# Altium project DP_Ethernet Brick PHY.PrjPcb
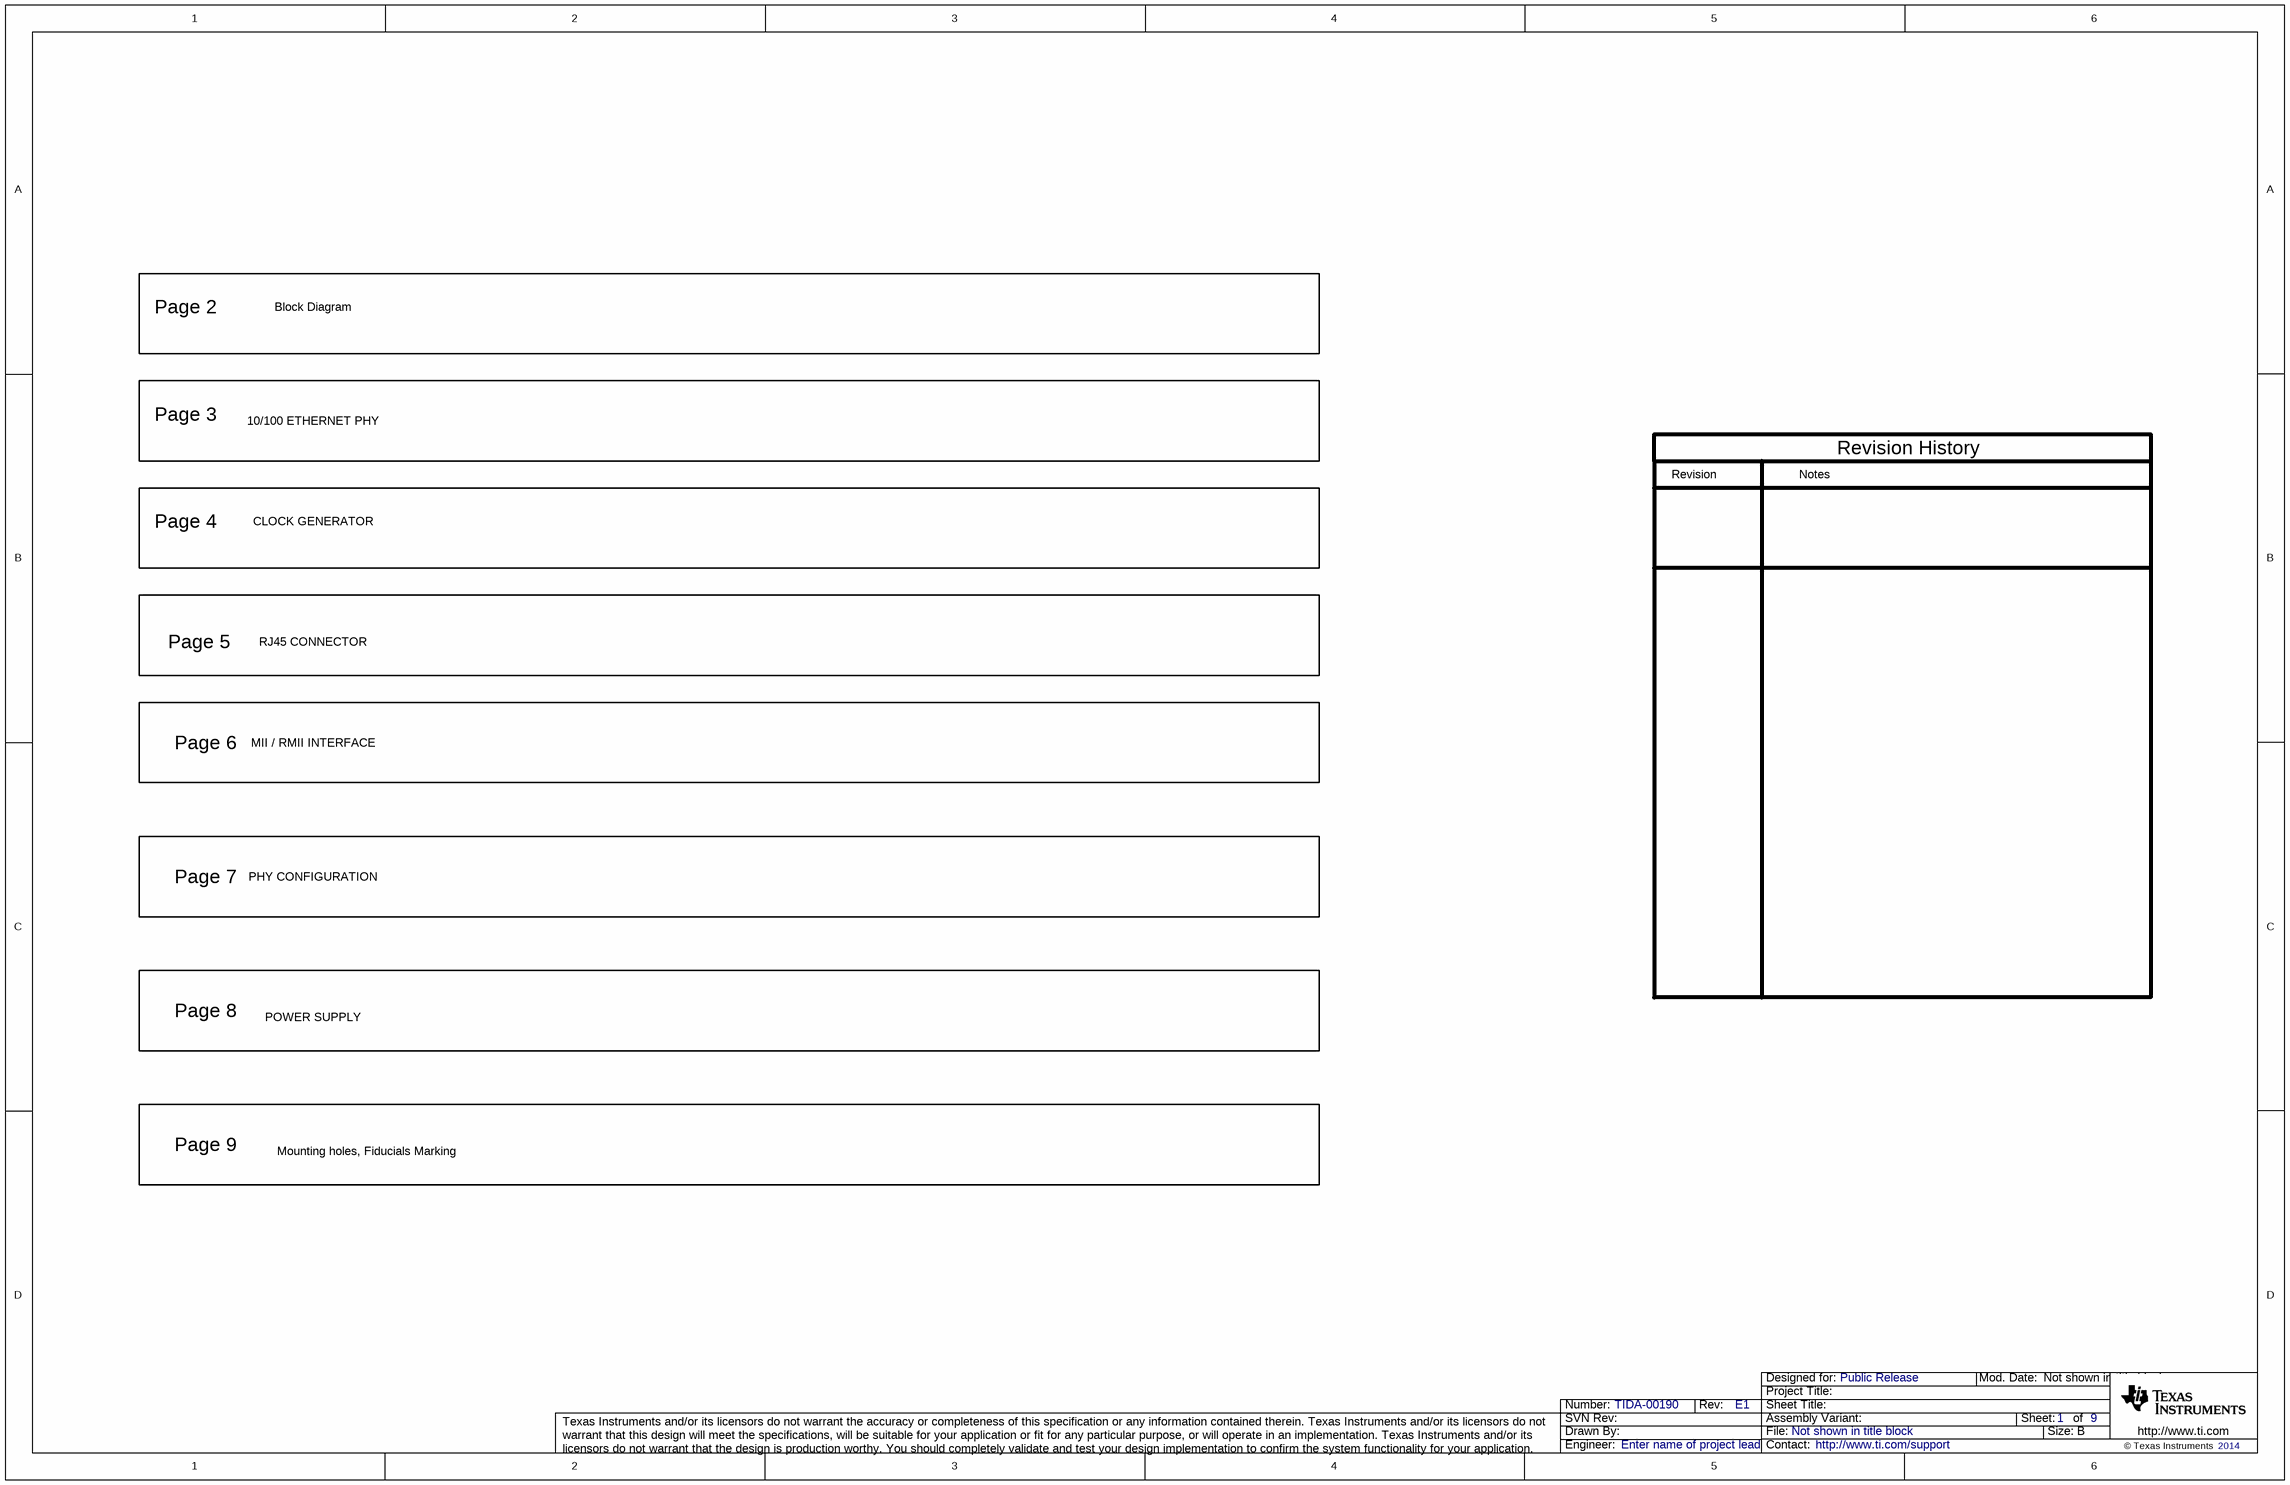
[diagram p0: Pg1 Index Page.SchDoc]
CopyrightYear: 2014; PCB_Layout: Who did the Layout?; PCB_Rev: E1; PRJ_Customer: Public Release; PRJ_Engineer: Enter name of project lead; PRJ_Number: TIDA-00190; SCH_Rev: E1; TechSupport: http://www.ti.com/support
9 sheets, 178 parts. Net scope: global (net labels, ports and power ports of the same name join across sheets).
Board file: ISE3009.PcbDoc
Sheets:
  Pg1 Index Page.SchDoc
  Pg2.SchDoc
  Pg3.SchDoc
  Pg4.SchDoc
  Pg5.SchDoc
  Pg6.SchDoc
  Pg7.SchDoc
  Pg8.SchDoc
  Pg9 Hardware.SchDoc

## Sheet Pg1 Index Page.SchDoc
size 431 x 279 mm; Date: Not shown in title block; ApprovedBy: Not shown in title block; CheckedBy: Not shown in title block; Author: Not shown in title block; CompanyName: Not shown in title block; Engineer: Not shown in title block; Organization: Not shown in title block; Address1: Not shown in title block; Address2: Not shown in title block; Address3: Not shown in title block; Address4: Not shown in title block; DocumentNumber: 1; Revision: Use project parameter SCH_Rev; SheetNumber: 1; SheetTotal: 9; PageSetup: Record=PageOptions|CenterHorizontal=True|CenterVertical=True|PrintScale=1.00|XCorrection=1.00|YCorrection=1.00|PrintKind=0|BorderSize=5000000|LeftOffset=0|BottomOffset=0|Orientation=2|PaperLength=1000|PaperWidth=1000|Scale=100|PaperSource=15|PrintQuality=600|MediaType=1|DitherType=10|PaperKind=Letter|PrintScaleMode=1

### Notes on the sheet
- Page 2
- Block Diagram
- Page 3
- 10/100 ETHERNET PHY
- Revision
- Notes
- Revision History
- Page 4
- CLOCK GENERATOR
- Page 5
- RJ45 CONNECTOR
- Page 6
- MII / RMII INTERFACE
- Page 7
- PHY CONFIGURATION
- Page 8
- POWER SUPPLY
- Page 9
- Mounting holes, Fiducials Marking

## Sheet Pg2.SchDoc
size 431 x 279 mm; Date: Not shown in title block; ApprovedBy: Not shown in title block; CheckedBy: Not shown in title block; Author: Not shown in title block; CompanyName: Not shown in title block; Engineer: Not shown in title block; Organization: Not shown in title block; Address1: Not shown in title block; Address2: Not shown in title block; Address3: Not shown in title block; Address4: Not shown in title block; DocumentNumber: 2; Revision: Use project parameter SCH_Rev; SheetNumber: 2; SheetTotal: 9; PageSetup: Record=PageOptions|CenterHorizontal=True|CenterVertical=True|PrintScale=1.00|XCorrection=1.00|YCorrection=1.00|PrintKind=0|BorderSize=5000000|LeftOffset=0|BottomOffset=0|Orientation=2|PaperLength=1000|PaperWidth=1000|Scale=100|PaperSource=15|PrintQuality=600|MediaType=1|DitherType=10|PaperKind=Letter|PrintScaleMode=1
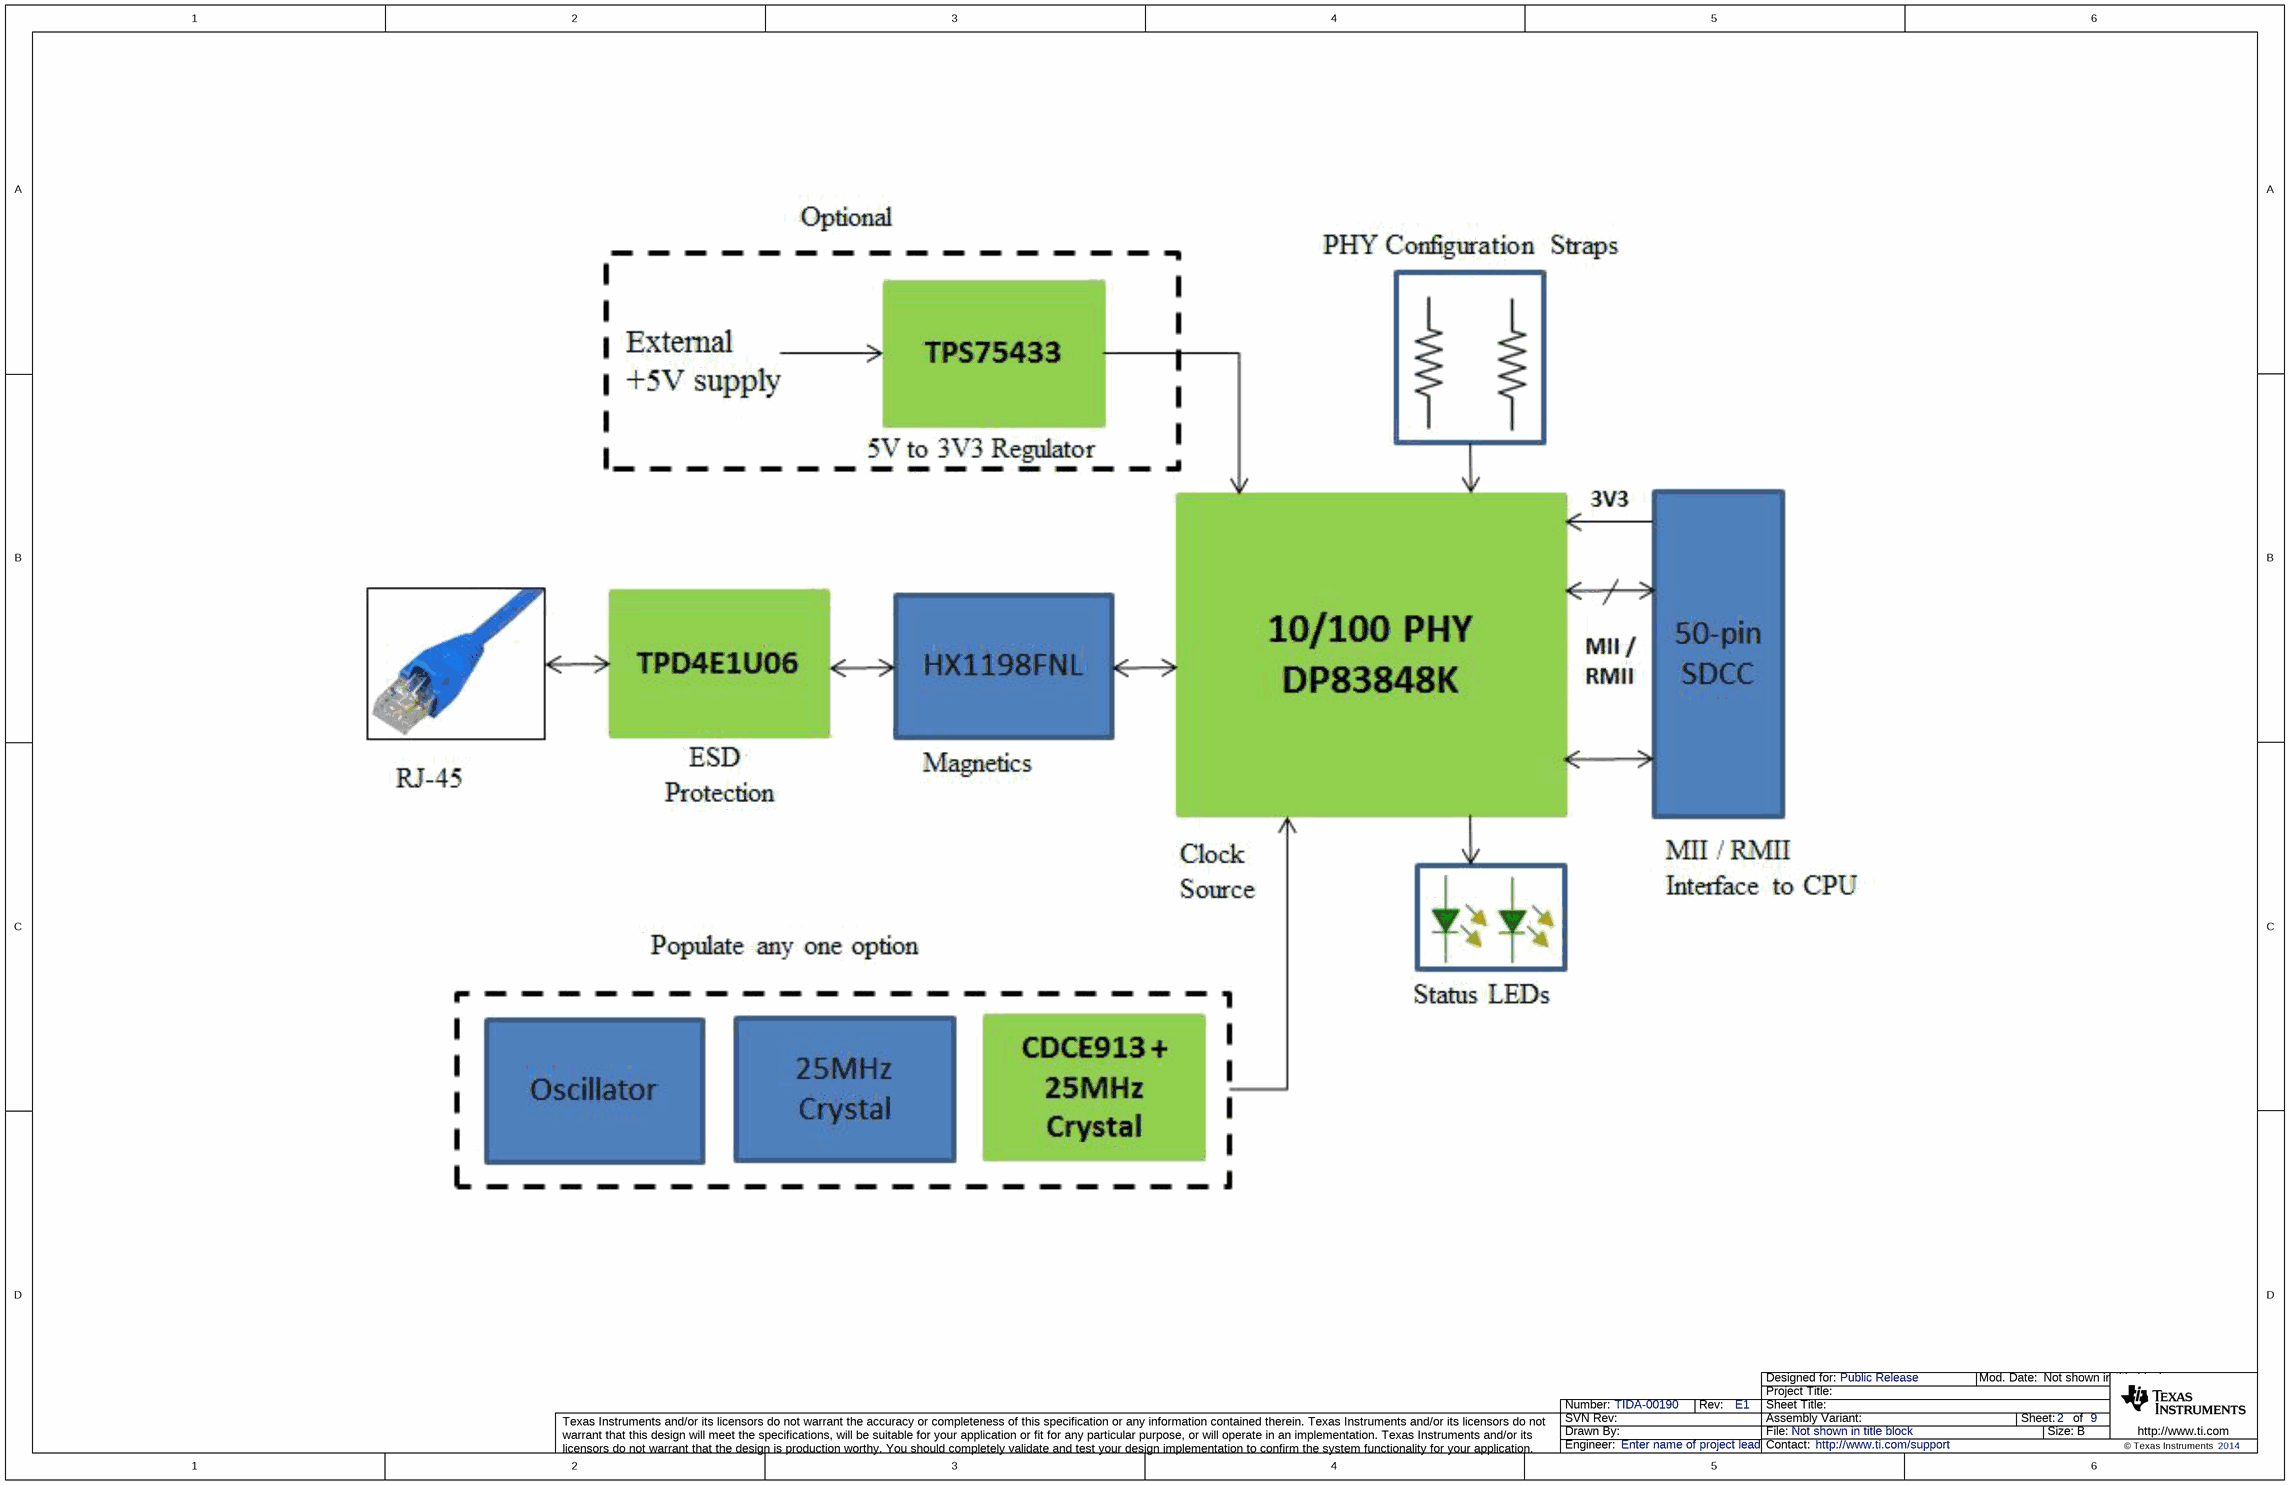
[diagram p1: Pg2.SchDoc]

## Sheet Pg3.SchDoc: 10/100 Ethernet PHY - DP83848J
size 558 x 431 mm; DocumentNumber: 9; SheetNumber: 3; SheetTotal: 9; PageSetup: Record=PageOptions|CenterHorizontal=True|CenterVertical=True|PrintScale=1.00|XCorrection=1.00|YCorrection=1.00|PrintKind=0|BorderSize=5000000|LeftOffset=0|BottomOffset=0|Orientation=2|PaperLength=1000|PaperWidth=1000|Scale=100|PaperSource=15|PrintQuality=600|MediaType=1|DitherType=10|PaperKind=Letter|PrintScaleMode=1
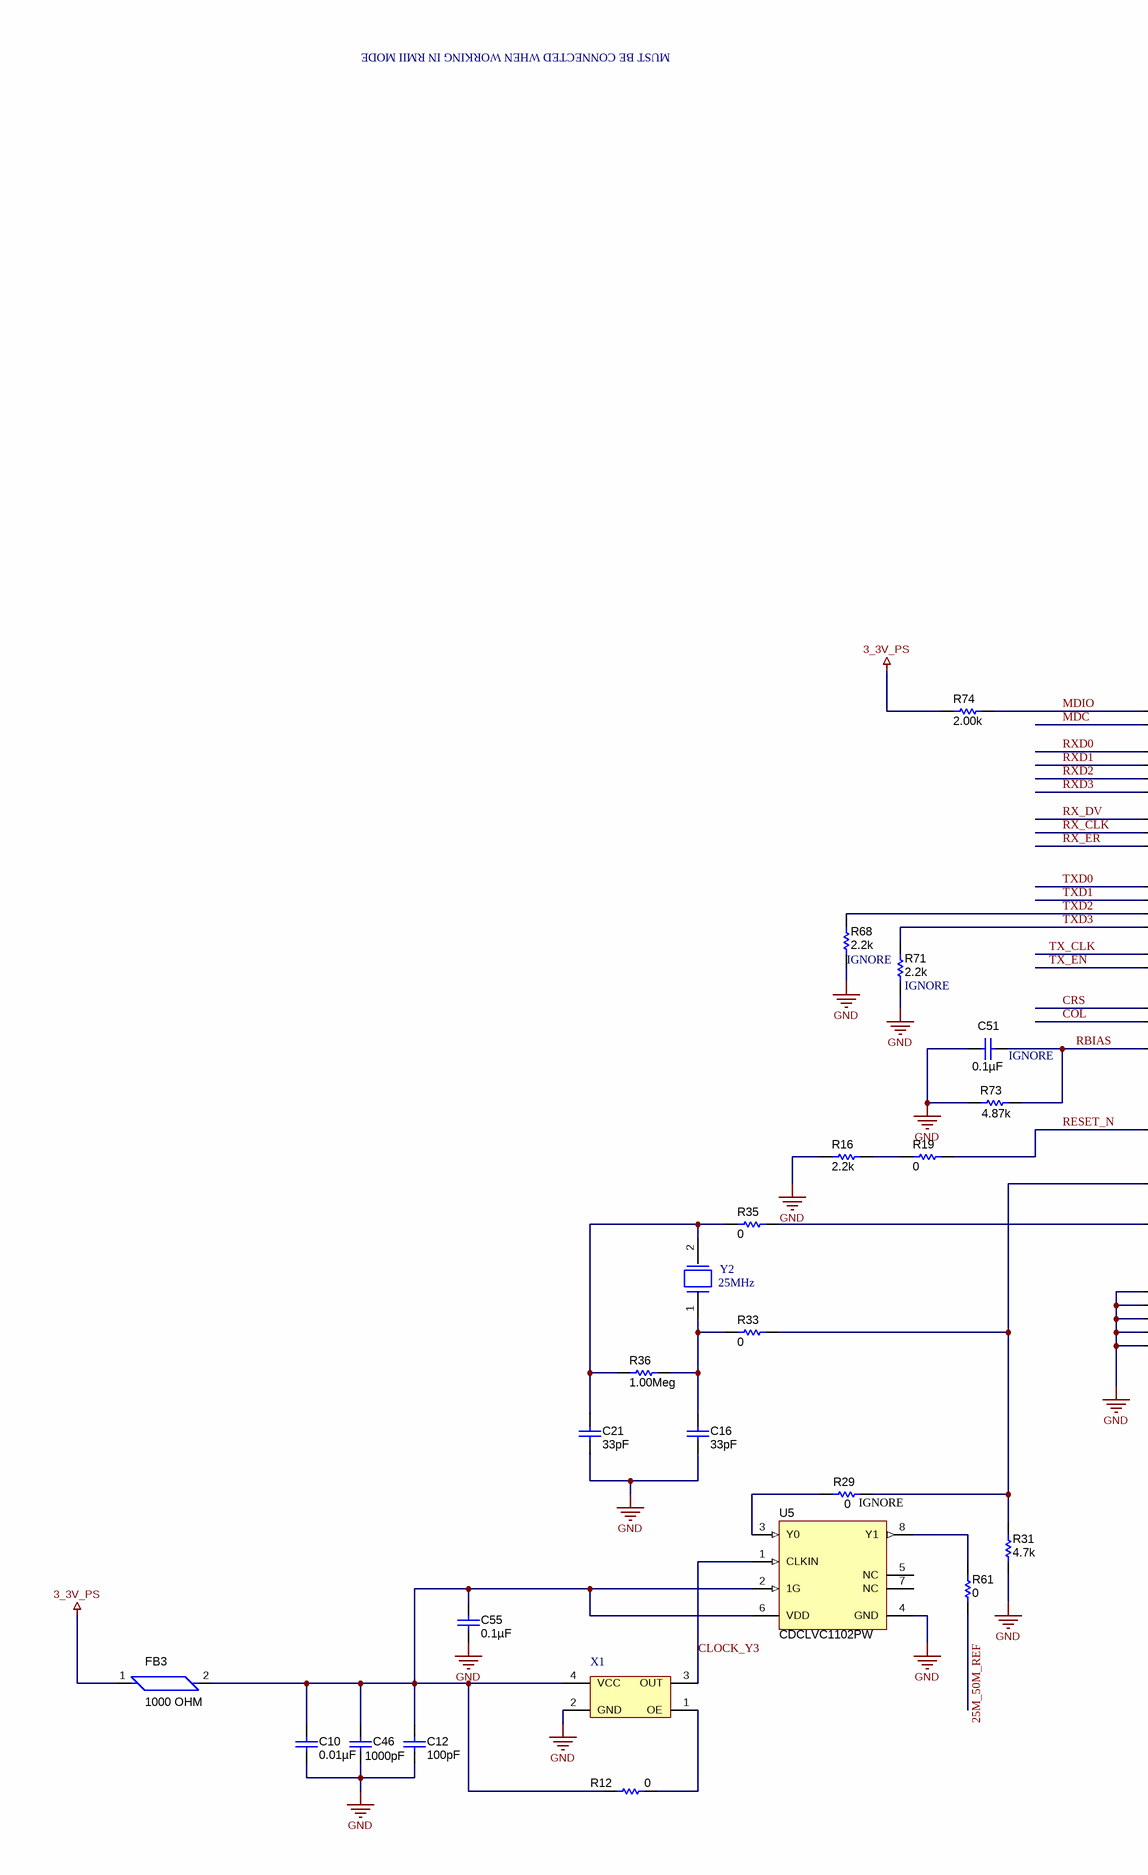
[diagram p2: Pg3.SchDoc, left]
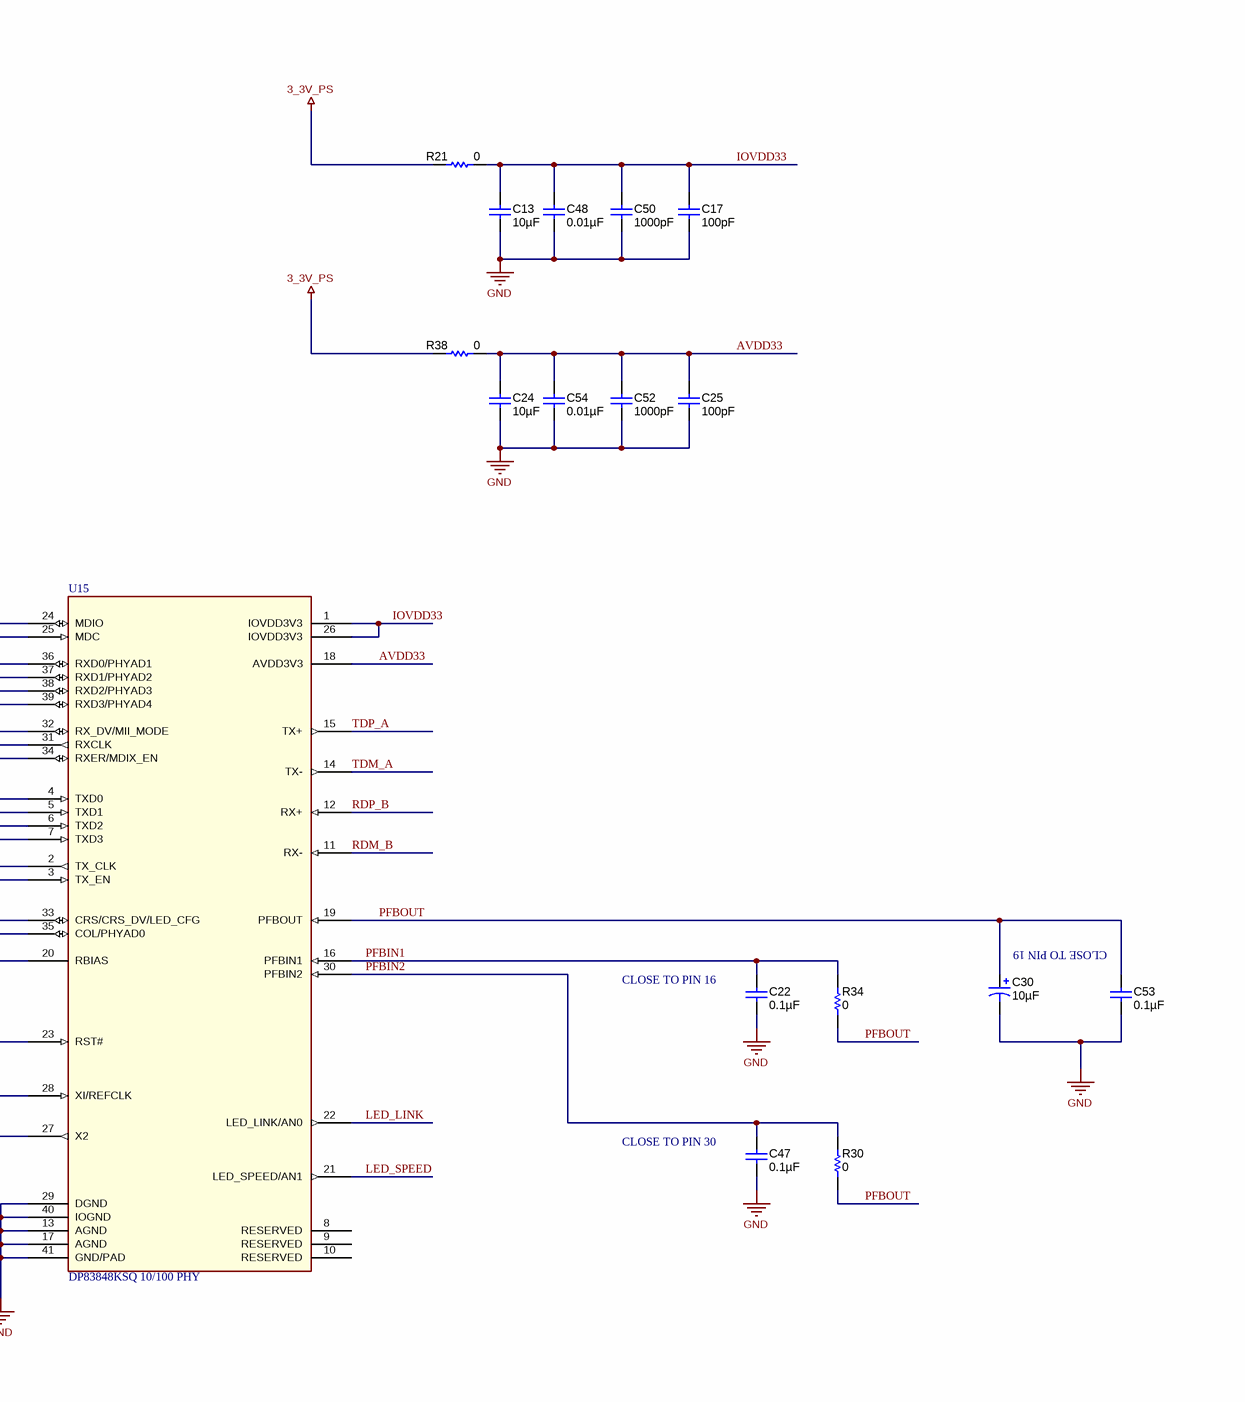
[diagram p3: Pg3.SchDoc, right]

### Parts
C10  ValueDisplayed: 0.01µF  [0402]  (hidden comment: GCM155R71H103KA55D)
C12  ValueDisplayed: 100pF  [0402]  (hidden comment: CC0402KRX7R9BB101)
C13  ValueDisplayed: 10µF  [1206]  (hidden comment: GMK316AB7106KL)
C16  ValueDisplayed: 33pF  [0603]  (hidden comment: 06035A330JAT2A)
C17  ValueDisplayed: 100pF  [0402]  (hidden comment: CC0402KRX7R9BB101)
C21  ValueDisplayed: 33pF  [0603]  (hidden comment: 06035A330JAT2A)
C22  ValueDisplayed: 0.1µF  [0603]  (hidden comment: C0603C104K4RACTU)
C24  ValueDisplayed: 10µF  [1206]  (hidden comment: GMK316AB7106KL)
C25  ValueDisplayed: 100pF  [0402]  (hidden comment: CC0402KRX7R9BB101)
C30  ValueDisplayed: 10µF  [3528-21]  (hidden comment: 293D106X9016B2TE3)
C46  ValueDisplayed: 1000pF  [0402]  (hidden comment: GRM155R61E102KA01D)
C47  ValueDisplayed: 0.1µF  [0603]  (hidden comment: C0603C104K4RACTU)
C48  ValueDisplayed: 0.01µF  [0402]  (hidden comment: GCM155R71H103KA55D)
C50  ValueDisplayed: 1000pF  [0402]  (hidden comment: GRM155R61E102KA01D)
C51  ValueDisplayed: 0.1µF  [0603]  (hidden comment: C0603C104K4RACTU)
C52  ValueDisplayed: 1000pF  [0402]  (hidden comment: GRM155R61E102KA01D)
C53  ValueDisplayed: 0.1µF  [0603]  (hidden comment: C0603C104K4RACTU)
C54  ValueDisplayed: 0.01µF  [0402]  (hidden comment: GCM155R71H103KA55D)
C55  ValueDisplayed: 0.1µF  [0603]  (hidden comment: C0603C104K4RACTU)
FB3  1000 OHM  [FB0603]
R12  value 0  [0603]  (hidden comment: CRCW06030000Z0EA)
R16  value 2.2k  [0402]  (hidden comment: CRCW04022K20JNED)
R19  value 0  [0603]  (hidden comment: CRCW06030000Z0EA)
R21  value 0  [0805_HV]  (hidden comment: RC0805JR-070RL)
R29  value 0  [0603]  (hidden comment: CRCW06030000Z0EA)
R30  value 0  [0805_HV]  (hidden comment: RC0805JR-070RL)
R31  value 4.7k  [0603]  (hidden comment: RC0603JR-074K7L)
R33  value 0  [0603]  (hidden comment: CRCW06030000Z0EA)
R34  value 0  [0805_HV]  (hidden comment: RC0805JR-070RL)
R35  value 0  [0603]  (hidden comment: CRCW06030000Z0EA)
R36  value 1.00Meg  [0402]  (hidden comment: CRCW04021M00FKED)
R38  value 0  [0805_HV]  (hidden comment: RC0805JR-070RL)
R61  value 0  [0603]  (hidden comment: CRCW06030000Z0EA)
R68  value 2.2k  [0402]  (hidden comment: CRCW04022K20JNED)
R71  value 2.2k  [0402]  (hidden comment: CRCW04022K20JNED)
R73  value 4.87k  [0603]  (hidden comment: CRCW06034K87FKEA)
R74  value 2.00k  [0402]  (hidden comment: CRCW04022K00FKED)
U5  CDCLVC1102PW  [PW0008A_N]
U15  DP83848KSQ 10/100 PHY  [QFN50P600X600X80-40N]
X1  HG-2150CA 25.000M-BXC3  [OSC_HG-2150CA]  (value not drawn)
Y2  value 25MHz  [XTAL_ATS250BSM-1E_1]  (hidden comment: XTAL-445I23D25M00000)

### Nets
3_3V_PS: FB3.1 R21.1 R38.1 R74.1
GND: C10.2 C12.2 C13.2 C16.2 C17.2 C21.2 C22.2 C24.2 C25.2 C30.2(-) C46.2 C47.2 C48.2 C50.2 C51.1 C52.2 C53.2 C54.2 C55.2 R16.2 R31.1 R68.1 R71.1 R73.1 U5.4(GND) U15.13(AGND) U15.17(AGND) U15.29(DGND) U15.40(IOGND) U15.41(GND/PAD) X1.2(GND)
25M_50M_REF: R61.1
AVDD33: C24.1 C25.1 C52.1 C54.1 R38.2 U15.18(AVDD3V3)
CLOCK_Y3: U5.1(CLKIN) X1.3(OUT)
COL: U15.35(COL/PHYAD0)
CRS: U15.33(CRS/CRS_DV/LED_CFG)
IOVDD33: C13.1 C17.1 C48.1 C50.1 R21.2 U15.1(IOVDD3V3) U15.26(IOVDD3V3)
LED_LINK: U15.22(LED_LINK/AN0)
LED_SPEED: U15.21(LED_SPEED/AN1)
MDC: U15.25(MDC)
MDIO: R74.2 U15.24(MDIO)
PFBIN1: C22.1 R34.2 U15.16(PFBIN1)
PFBIN2: C47.1 R30.2 U15.30(PFBIN2)
PFBOUT: C30.1(+) C53.1 R30.1 R34.1 U15.19(PFBOUT)
RBIAS: C51.2 R73.2 U15.20(RBIAS)
RDM_B: U15.11(RX-)
RDP_B: U15.12(RX+)
RESET_N: R19.2 U15.23(RST#)
RX_CLK: U15.31(RXCLK)
RX_DV: U15.32(RX_DV/MII_MODE)
RX_ER: U15.34(RXER/MDIX_EN)
RXD0: U15.36(RXD0/PHYAD1)
RXD1: U15.37(RXD1/PHYAD2)
RXD2: U15.38(RXD2/PHYAD3)
RXD3: U15.39(RXD3/PHYAD4)
TDM_A: U15.14(TX-)
TDP_A: U15.15(TX+)
TX_CLK: U15.2(TX_CLK)
TX_EN: U15.3(TX_EN)
TXD0: U15.4(TXD0)
TXD1: U15.5(TXD1)
TXD2: R68.2 U15.6(TXD2)
TXD3: R71.2 U15.7(TXD3)
NetC10_1: C10.1 C12.1 C46.1 C55.1 FB3.2 R12.1 U5.2(1G) U5.6(VDD) X1.4(VCC)
NetC16_1: C16.1 R33.2 R36.2 Y2.1
NetC21_1: C21.1 R35.2 R36.1 Y2.2
NetR12_2: R12.2 X1.1(OE)
NetR16_1: R16.1 R19.1
NetR29_1: R29.1 U5.3(Y0)
NetR29_2: R29.2 R31.2 R33.1 U15.28(XI/REFCLK)
NetR35_1: R35.1 U15.27(X2)
NetR61_2: R61.2 U5.8(Y1)

Not connected (* = marked no-connect by the designer): U5 5(NC) 7(NC); U15 8(RESERVED) 9(RESERVED) 10(RESERVED)

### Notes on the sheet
- MUST BE CONNECTED WHEN WORKING IN RMII MODE
- (near C22) CLOSE TO PIN 16
- CLOSE TO PIN 19
- (near C47) CLOSE TO PIN 30

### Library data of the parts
C10 C48 C54 = GCM155R71H103KA55D: CAP, CERM, 0.01uF, 50V, +/-10%, C0G/NP0, 0402; Manufacturer: MuRata; Polarized: N; CompType: Capacitor; U/M: EA; Cap_F: 0.00000001; Tolerance_%: 10; Value1: Unknown; VDC_V: 50; TaMin_C: -55; TaMax_C: 125
C12 C17 C25 = CC0402KRX7R9BB101: CAP, CERM, 100pF, 50V, +/-10%, X7R, 0402; Manufacturer: Yageo America; Polarized: N; CompType: Capacitor; U/M: EA; Cap_F: 0.0000000001; Tolerance_%: 10; Value1: Unknown; VDC_V: 50; TaMin_C: -55; TaMax_C: 125
C13 C24 = GMK316AB7106KL: CAP, CERM, 10uF, 35V, +/-10%, X7R, 1206; Manufacturer: Taiyo Yuden; Polarized: N; CompType: Capacitor; U/M: EA; Cap_F: 0.00001; Tolerance_%: 10; Value1: Unknown; VDC_V: 35; TaMin_C: -55; TaMax_C: 125
C16 C21 = 06035A330JAT2A: CAP, CERM, 33pF, 50V, +/-5%, C0G/NP0, 0603; Manufacturer: AVX; Polarized: N; CompType: Capacitor; U/M: EA; Cap_F: 0.000000000033; Tolerance_%: 5; ESR_Ohm: 0.209; Value1: 0.209 ohm; VDC_V: 50; TaMin_C: -55; TaMax_C: 125
C22 C47 C51 C53 C55 = C0603C104K4RACTU: CAP, CERM, 0.1uF, 16V, +/-10%, X7R, 0603; Manufacturer: Kemet; Polarized: N; CompType: Capacitor; U/M: EA; Cap_F: 0.0000001; Tolerance_%: 10; Value1: Unknown; VDC_V: 16; TaMin_C: -55; TaMax_C: 125
C30 = 293D106X9016B2TE3: CAP, TA, 10uF, 16V, +/-10%, 2 ohm, SMD; Manufacturer: Vishay-Sprague; Polarized: Y; CompType: Capacitor; U/M: EA; Cap_F: 0.00001; Tolerance_%: 10; Value1: 2 ohm; VDC_V: 16; ESR_Ohm: 2; IRMS_A: 0.21; TaMin_C: -55; TaMax_C: 125; Cap_Case: B
C46 C50 C52 = GRM155R61E102KA01D: CAP, CERM, 1000pF, 25V, +/-10%, X5R, 0402; Manufacturer: MuRata; Polarized: N; CompType: Capacitor; U/M: EA; Cap_F: 0.000000001; Tolerance_%: 10; Value1: Unknown; VDC_V: 25; TaMin_C: -55; TaMax_C: 85
FB3 = MMZ1608B102C: FERRITE CHIP 1000 OHM 300MA 0603; Manufacturer: TDK Corporation; CompType: Ferrite Bead
R12 R19 R29 R33 R35 R61 = CRCW06030000Z0EA: RES, 0 ohm, 5%, 0.1W, 0603; Manufacturer: Vishay-Dale; CompType: Resistor; Value_Code: 0000; Tolerance_%: 5; Power_W: 0.1; VDC_V: 75; TempCo: 200 ppm/C; EIA_Code: E24; U/M: EA
R16 R68 R71 = CRCW04022K20JNED: RES, 2.2k ohm, 5%, 0.063W, 0402; Manufacturer: Vishay-Dale; CompType: Resistor; Res_ohm: 2200; Value_Code: 2k20; Tolerance_%: 5; Power_W: 0.063; VDC_V: 50; TempCo: 200 ppm/C; EIA_Code: E24; U/M: EA
R21 R30 R34 R38 = RC0805JR-070RL: RES, 0 ohm, 5%, 0.125W, 0805; Manufacturer: Yageo America; CompType: Resistor; Value_Code: 0000; Tolerance_%: 5; Power_W: 0.125; VDC_V: 150; TempCo: 200 ppm/C; EIA_Code: E24; U/M: EA
R31 = RC0603JR-074K7L: RES, 4.7k ohm, 5%, 0.1W, 0603; Manufacturer: Yageo America; CompType: Resistor; Res_ohm: 4700; Value_Code: 4k70; Tolerance_%: 5; Power_W: 0.1; VDC_V: 50; TempCo: 100 ppm/C; EIA_Code: E24; U/M: EA
R36 = CRCW04021M00FKED: RES, 1.00Meg ohm, 1%, 0.063W, 0402; Manufacturer: Vishay-Dale; CompType: Resistor; Res_ohm: 1000000; Value_Code: 1M00; Tolerance_%: 1; Power_W: 0.063; VDC_V: 50; TempCo: 100 ppm/C; EIA_Code: E96; U/M: EA
R73 = CRCW06034K87FKEA: RES, 4.87k ohm, 1%, 0.1W, 0603; Manufacturer: Vishay-Dale; CompType: Resistor; Res_ohm: 4870; Value_Code: 4k87; Tolerance_%: 1; Power_W: 0.1; VDC_V: 75; TempCo: 100 ppm/C; EIA_Code: E96; U/M: EA
R74 = CRCW04022K00FKED: RES, 2.00k ohm, 1%, 0.063W, 0402; Manufacturer: Vishay-Dale; CompType: Resistor; Res_ohm: 2000; Value_Code: 2k00; Tolerance_%: 1; Power_W: 0.063; VDC_V: 50; TempCo: 100 ppm/C; EIA_Code: E96; U/M: EA
U5 = CDCLVC1102PW: 3.3 V and 2.5 V LVCMOS High-Performance Clock Buffer Family, PW0008A; Alternate Manufacturer: None; Manufacturer: Texas Instruments; SymbolCreator: a0799628; CompType: IC; U/M: EA
U15 = DP83848J: TI DP83848J 10/100 PHY; Manufacturer: Texas Instruments; Manufacturer PN: DP83848KSQ/NOPB
X1 = HG-2150CA 25.000M-BXC3: OSC 25.00 MHZ 3.3V HIGH STAB SMD; Manufacturer: EPSON; Value: 25MHz
Y2 = XTAL-NX5032GA: CRYSTAL 25.0MHZ 18PF SMD; Manufacturer: CTS-Frequency Controls

## Sheet Pg4.SchDoc
size 431 x 279 mm; Date: Not shown in title block; ApprovedBy: Not shown in title block; CheckedBy: Not shown in title block; Author: Not shown in title block; CompanyName: Not shown in title block; Engineer: Not shown in title block; Organization: Not shown in title block; Address1: Not shown in title block; Address2: Not shown in title block; Address3: Not shown in title block; Address4: Not shown in title block; DocumentNumber: 4; Revision: Use project parameter SCH_Rev; SheetNumber: 4; SheetTotal: 9; PageSetup: Record=PageOptions|CenterHorizontal=True|CenterVertical=True|PrintScale=1.00|XCorrection=1.00|YCorrection=1.00|PrintKind=0|BorderSize=5000000|LeftOffset=0|BottomOffset=0|Orientation=2|PaperLength=1000|PaperWidth=1000|Scale=100|PaperSource=15|PrintQuality=600|MediaType=1|DitherType=10|PaperKind=Letter|PrintScaleMode=1
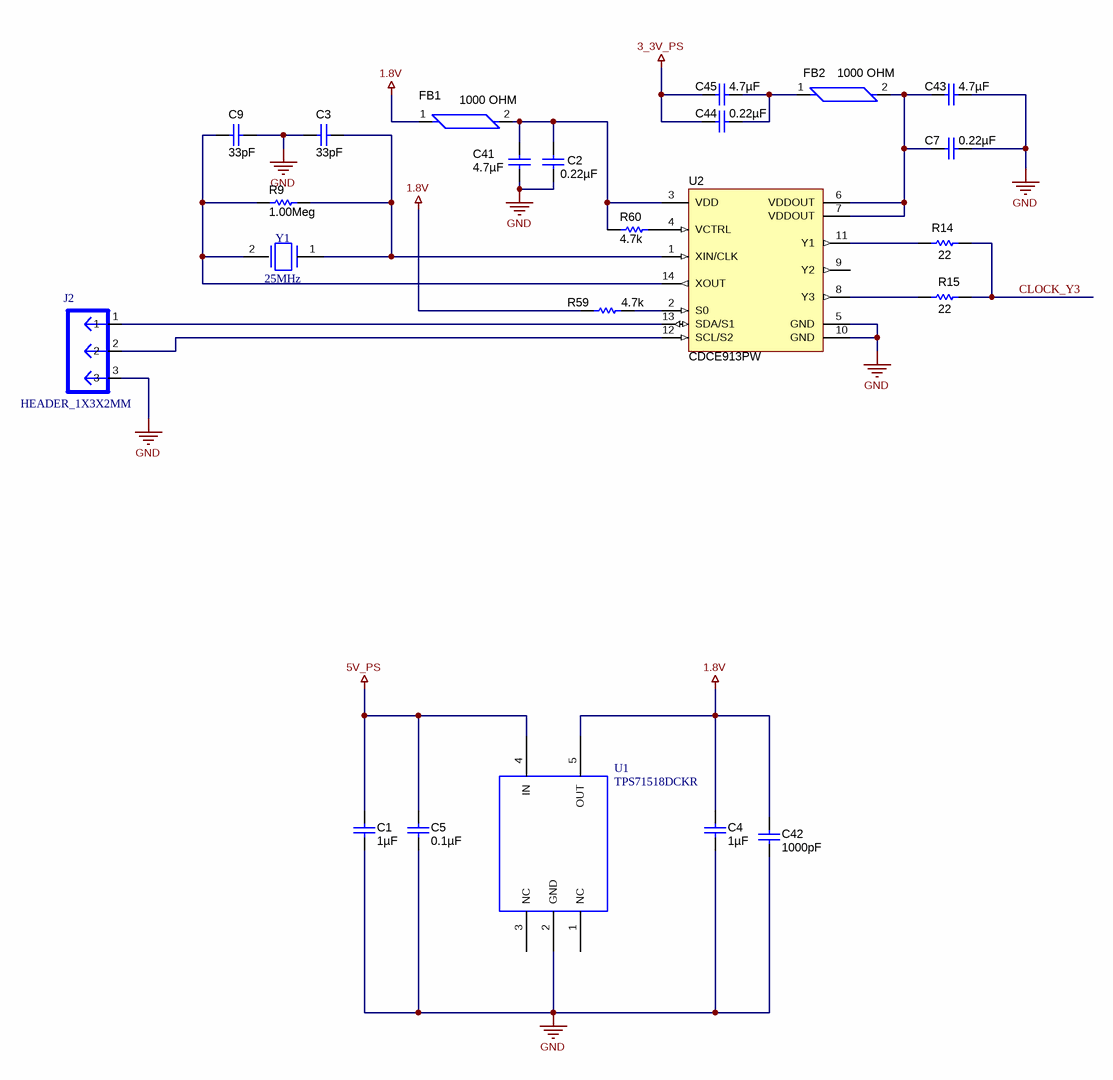
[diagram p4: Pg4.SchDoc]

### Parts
C1  ValueDisplayed: 1µF  [1206]  (hidden comment: GRM31MR61C105KA0)
C2  ValueDisplayed: 0.22µF  [0603]  (hidden comment: C0603C224K9RACTU)
C3  ValueDisplayed: 33pF  [0603]  (hidden comment: 06035A330JAT2A)
C4  ValueDisplayed: 1µF  [1206]  (hidden comment: GRM31MR61C105KA0)
C5  ValueDisplayed: 0.1µF  [0603]  (hidden comment: C0603C104Z4VACTU)
C7  ValueDisplayed: 0.22µF  [0603]  (hidden comment: C0603C224K9RACTU)
C9  ValueDisplayed: 33pF  [0603]  (hidden comment: 06035A330JAT2A)
C41  ValueDisplayed: 4.7µF  [0603]  (hidden comment: C0603C475K9PACTU)
C42  ValueDisplayed: 1000pF  [0402]  (hidden comment: GRM155R61E102KA01D)
C43  ValueDisplayed: 4.7µF  [0603]  (hidden comment: C0603C475K9PACTU)
C44  ValueDisplayed: 0.22µF  [0603]  (hidden comment: C0603C224K9RACTU)
C45  ValueDisplayed: 4.7µF  [0603]  (hidden comment: C0603C475K9PACTU)
FB1  value 1000 OHM  [FB0603]
FB2  value 1000 OHM  [FB0603]
J2  HEADER_1X3X2MM  [HEADER_1X3X2MM]
R9  value 1.00Meg  [0402]  (hidden comment: CRCW04021M00FKED)
R14  value 22  [0402]  (hidden comment: CRCW040222R0JNED)
R15  value 22  [0402]  (hidden comment: CRCW040222R0JNED)
R59  value 4.7k  [0603]  (hidden comment: RC0603JR-074K7L)
R60  value 4.7k  [0603]  (hidden comment: RC0603JR-074K7L)
U1  TPS71518DCKR  [SOP_5P.65MM(DCK)]
U2  CDCE913PW  [PW0014A_N]
Y1  value 25MHz  [XTAL_ATS250BSM-1E_1]  (hidden comment: XTAL-ATS250BSM-1E)

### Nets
1.8V: C4.1 C42.1 FB1.1 R59.2 U1.5(OUT)
3_3V_PS: C44.2 C45.2
5V_PS: C1.1 C5.1 U1.4(IN)
GND: C1.2 C2.1 C3.2 C4.2 C5.2 C7.1 C9.2 C41.1 C42.2 C43.1 J2.3 U1.2(GND) U2.5(GND) U2.10(GND)
CLOCK_Y3: R14.2 R15.2
NetC2_2: C2.2 C41.2 FB1.2 R60.2 U2.3(VDD)
NetC3_1: C3.1 R9.2 U2.1(XIN/CLK) Y1.1
NetC7_2: C7.2 C43.2 FB2.2 U2.6(VDDOUT) U2.7(VDDOUT)
NetC9_1: C9.1 R9.1 U2.14(XOUT) Y1.2
NetC44_1: C44.1 C45.1 FB2.1
NetJ2_1: J2.1 U2.13(SDA/S1)
NetJ2_2: J2.2 U2.12(SCL/S2)
NetR14_1: R14.1 U2.11(Y1)
NetR15_1: R15.1 U2.8(Y3)
NetR59_1: R59.1 U2.2(S0)
NetR60_1: R60.1 U2.4(VCTRL)

Not connected (* = marked no-connect by the designer): U1 1(NC) 3(NC); U2 9(Y2)

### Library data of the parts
C1 C4 = GRM319R61A105KA01D: CAP CER 1UF 16V 10% X5R 1206; Manufacturer: Murata Electronics; Polarized: N; CompType: Capacitor; U/M: EA; Cap_F: 0.000001; Tolerance_%: 10; Value1: Unknown; Value2: 10V; TaMin_C: -55; TaMax_C: 85
C2 C7 C44 = GRM188R70J224KA88D: CAP CER 0.22UF 6.3V 10% X7R 0603; Manufacturer: Kemet; Polarized: N; CompType: Capacitor; U/M: EA; Cap_F: 0.00000022; Tolerance_%: 10; Value1: Unknown; VDC_V: 6.3; TaMin_C: -55; TaMax_C: 125
C3 C9 = 06035A330JAT2A: as C16 on sheet Pg3
C5 = C0603C104Z4VACTU: CAP, CERM, 0.1uF, 16V, +80/-20%, Y5V, 0603; Manufacturer: Kemet; Polarized: N; CompType: Capacitor; U/M: EA; Cap_F: 0.0000001; Tolerance_%: 80; Value1: Unknown; VDC_V: 16; TaMin_C: -30; TaMax_C: 85
C41 C43 C45 = C0603C475K9PACTU: CAP, CERM, 4.7uF, 6.3V, +/-10%, X5R, 0603; Manufacturer: Kemet; Polarized: N; CompType: Capacitor; U/M: EA; Cap_F: 0.0000047; Tolerance_%: 10; ESR_Ohm: 0.006; Value1: 0.006 ohm; VDC_V: 6.3; IRMS_A: 7.24; TaMin_C: -55; TaMax_C: 85
C42 = GRM155R61E102KA01D: as C46 on sheet Pg3
FB1 FB2 = MMZ1608B102C: as FB3 on sheet Pg3
J2 = HEADER_1X3X2MM: CONN HEADER 3POS 2MM VERT T/H; Manufacturer: 3M; PartNumber: 951103-8622-AR; area: 19600; Value: 951103-8622-AR
R9 = CRCW04021M00FKED: as R36 on sheet Pg3
R14 R15 = CRCW040222R0JNED: RES, 22 ohm, 5%, 0.063W, 0402; Manufacturer: Vishay-Dale; CompType: Resistor; Value_Code: 22R0; Tolerance_%: 5; Power_W: 0.063; VDC_V: 50; TempCo: 200 ppm/C; EIA_Code: E24; U/M: EA
R59 R60 = RC0603JR-074K7L: as R31 on sheet Pg3
U1 = TPS71533DCK: IC REG LDO 1.8V 50MA SC70-5; Manufacturer: TI; Alternate Manufacturer: None; Area: 30405
U2 = CDCE913PW: Programmable 1-PLL VCXO Clock Synthesizer With 1.8-V, 2.5-V, and 3.3-V Outputs, PW0014A; Alternate Manufacturer: None; Manufacturer: Texas Instruments; SymbolCreator: a0411947; CompType: IC; U/M: EA
Y1 = XTAL-NX5032GA: CRYSTAL 25.0MHZ 18PF SMD; Manufacturer: CTS-Frequency Controls; PartNumber: 445I23D25M00000

## Sheet Pg5.SchDoc
size A4; Date: Not shown in title block; ApprovedBy: Not shown in title block; CheckedBy: Not shown in title block; Author: Not shown in title block; CompanyName: Not shown in title block; Engineer: Not shown in title block; Organization: Not shown in title block; Address1: Not shown in title block; Address2: Not shown in title block; Address3: Not shown in title block; Address4: Not shown in title block; DocumentNumber: 5; Revision: Use project parameter SCH_Rev; SheetNumber: 5; SheetTotal: 9; PageSetup: Record=PageOptions|CenterHorizontal=True|CenterVertical=True|PrintScale=0.59|XCorrection=1.00|YCorrection=1.00|PrintKind=0|BorderSize=5000000|LeftOffset=0|BottomOffset=0|Orientation=2|PaperLength=1000|PaperWidth=1000|Scale=100|PaperSource=15|PrintQuality=600|MediaType=1|DitherType=10|PaperKind=Letter|PrintScaleMode=1
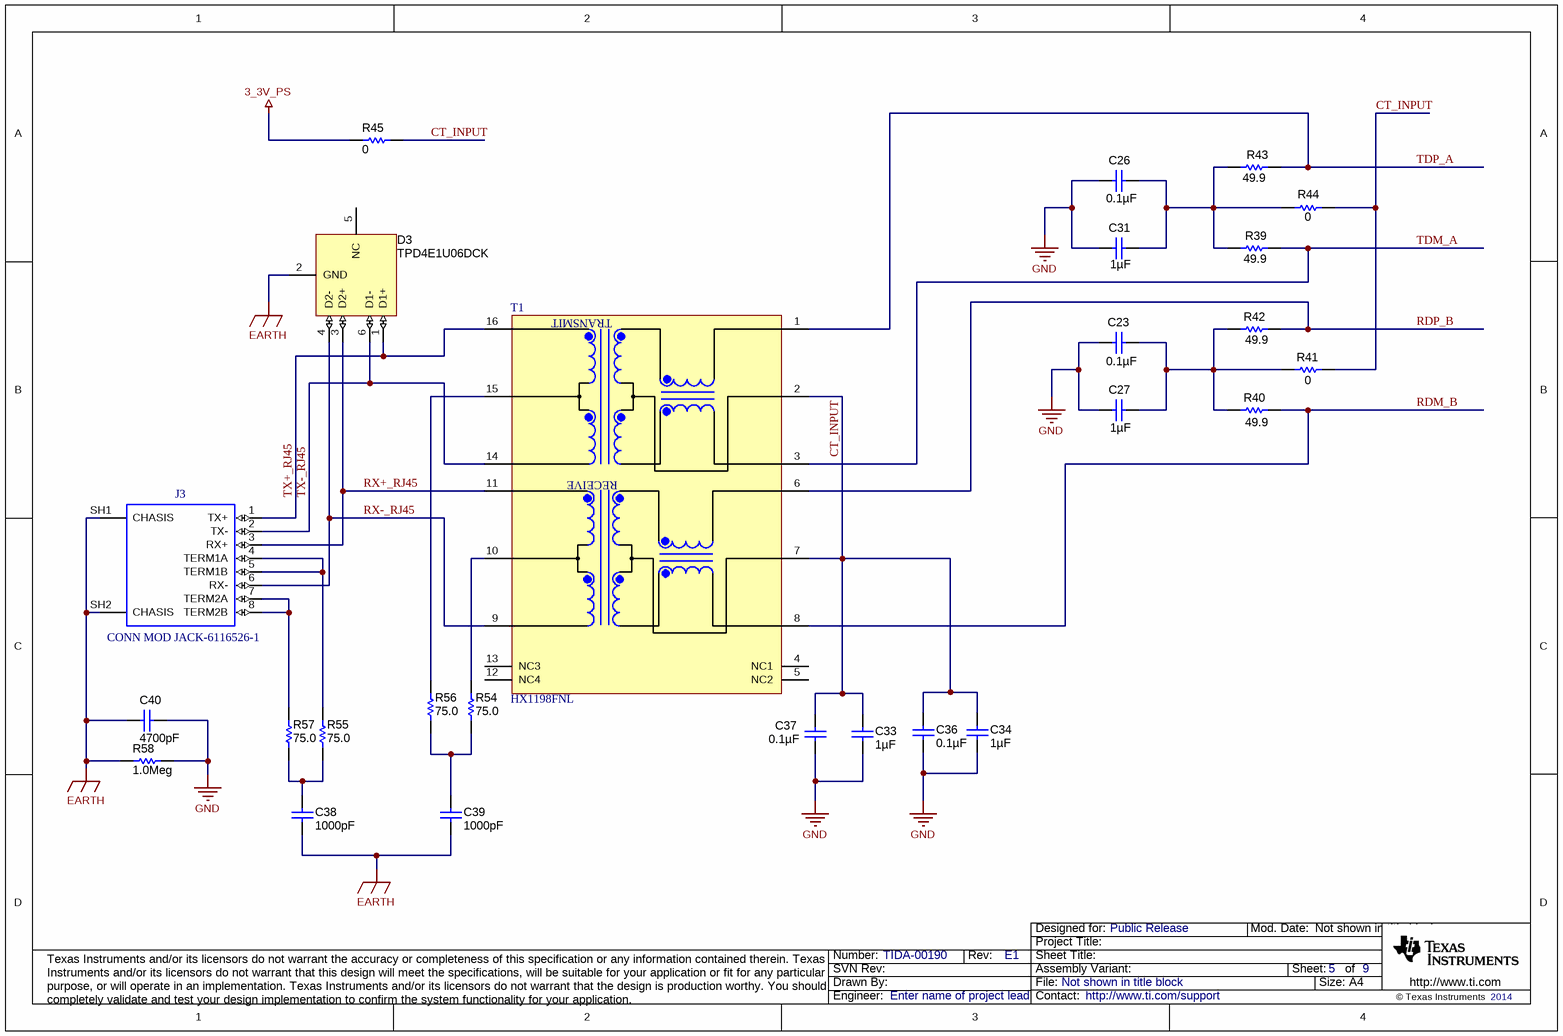
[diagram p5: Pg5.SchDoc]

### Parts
C23  ValueDisplayed: 0.1µF  [0402]  (hidden comment: C1005X5R1A104K)
C26  ValueDisplayed: 0.1µF  [0402]  (hidden comment: C1005X5R1A104K)
C27  ValueDisplayed: 1µF  [0603]  (hidden comment: GRM185R60J105KE26D)
C31  ValueDisplayed: 1µF  [0603]  (hidden comment: GRM185R60J105KE26D)
C33  ValueDisplayed: 1µF  [0603]  (hidden comment: GRM185R60J105KE26D)
C34  ValueDisplayed: 1µF  [0603]  (hidden comment: GRM185R60J105KE26D)
C36  ValueDisplayed: 0.1µF  [0402]  (hidden comment: C1005X5R1A104K)
C37  ValueDisplayed: 0.1µF  [0402]  (hidden comment: C1005X5R1A104K)
C38  ValueDisplayed: 1000pF  [1812]  (hidden comment: 1812GC102KA1)
C39  ValueDisplayed: 1000pF  [1812]  (hidden comment: 1812GC102KA1)
C40  ValueDisplayed: 4700pF  [1812]  (hidden comment: 1812GC472KA1)
D3  TPD4E1U06DCK  [DCK0006A_N]
J3  CONN MOD JACK-6116526-1  [TE_6116526-1]
R39  value 49.9  [0402]  (hidden comment: CRCW040249R9FKED)
R40  value 49.9  [0402]  (hidden comment: CRCW040249R9FKED)
R41  value 0  [0603]  (hidden comment: CRCW06030000Z0EA)
R42  value 49.9  [0402]  (hidden comment: CRCW040249R9FKED)
R43  value 49.9  [0402]  (hidden comment: CRCW040249R9FKED)
R44  value 0  [0603]  (hidden comment: CRCW06030000Z0EA)
R45  value 0  [0603]  (hidden comment: CRCW06030000Z0EA)
R54  value 75.0  [0603]  (hidden comment: RC0603FR-0775RL)
R55  value 75.0  [0603]  (hidden comment: RC0603FR-0775RL)
R56  value 75.0  [0603]  (hidden comment: RC0603FR-0775RL)
R57  value 75.0  [0603]  (hidden comment: RC0603FR-0775RL)
R58  value 1.0Meg  [1206]  (hidden comment: CRCW12061M00JNEA)
T1  HX1198FNL  [XFMR_ HX1198FNL]

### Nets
3_3V_PS: R45.2
EARTH: C38.2 C39.2 C40.2 D3.2(GND) J3.SH1(CHASIS) J3.SH2(CHASIS) R58.2
GND: C23.2 C26.2 C27.2 C31.2 C33.2 C34.2 C36.2 C37.2 C40.1 R58.1
CT_INPUT: C33.1 C34.1 C36.1 C37.1 R41.1 R44.1 R45.1 T1.2(TCT) T1.7(RCT)
RDM_B: R40.2 T1.8(RD-)
RDP_B: R42.2 T1.6(RD+)
RX+_RJ45: D3.3(D2+) J3.3(RX+) T1.11(RX+)
RX-_RJ45: D3.4(D2-) J3.6(RX-) T1.9(RX-)
TDM_A: R39.2 T1.3(TD-)
TDP_A: R43.2 T1.1(TD+)
TX+_RJ45: D3.1(D1+) J3.1(TX+) T1.16(TX+)
TX-_RJ45: D3.6(D1-) J3.2(TX-) T1.14(TX-)
NetC23_1: C23.1 C27.1 R40.1 R41.2 R42.1
NetC26_1: C26.1 C31.1 R39.1 R43.1 R44.2
NetC38_1: C38.1 R55.1 R57.1
NetC39_1: C39.1 R54.1 R56.1
NetJ3_4: J3.4(TERM1A) J3.5(TERM1B) R55.2
NetJ3_7: J3.7(TERM2A) J3.8(TERM2B) R57.2
NetR54_2: R54.2 T1.10(CMT)
NetR56_2: R56.2 T1.15(CMT)

Not connected (* = marked no-connect by the designer): D3 5(NC); T1 4(NC1) 5(NC2) 12(NC4) 13(NC3)

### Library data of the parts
C23 C26 C36 C37 = C1005X5R1A104K: CAP, CERM, 0.1uF, 10V, +/-10%, X5R, 0402; Manufacturer: TDK; Polarized: N; CompType: Capacitor; U/M: EA; Cap_F: 0.0000001; Tolerance_%: 10; ESR_Ohm: 0.0186; Value1: 0.0186 ohm; TaMin_C: -55; TaMax_C: 85
C27 C31 C33 C34 = GRM185R60J105KE26D: CAP, CERM, 1uF, 6.3V, +/-10%, X5R, 0603; Manufacturer: MuRata; Polarized: N; CompType: Capacitor; U/M: EA; Cap_F: 0.000001; Tolerance_%: 10; Value1: Unknown; VDC_V: 6.3; TaMin_C: -55; TaMax_C: 85
C38 C39 = 1812GC102KA1: CAP, CERM, 1000pF, 2000V, +/-10%, X7R, 1812; Manufacturer: AVX; Polarized: N; CompType: Capacitor; U/M: EA; Cap_F: 0.000000001; Tolerance_%: 10; Value1: Unknown; VDC_V: 2000; TaMin_C: -55; TaMax_C: 125
C40 = 1812GC472KA1: CAP, CERM, 4700pF, 2000V, +/-10%, X7R, 1812; Manufacturer: AVX; Polarized: N; CompType: Capacitor; U/M: EA; Cap_F: 0.0000000047; Tolerance_%: 10; Value1: Unknown; VDC_V: 2000; TaMin_C: -55; TaMax_C: 125
D3 = TPD4E1U06DCK: Quad Channel High Speed ESD Protection Device, DCK0006A; Alternate Manufacturer: None; Manufacturer: Texas Instruments; SymbolCreator: a0411947; CompType: IC; U/M: EA
J3 = RJ45_NOMAG_NOLED: CONN MOD JACK R/A 8P8C SHIELDED; Manufacturer: TE Connectivity; PCB DECAL: 406541; GNUM: G20-8RJ45-ENET-AAA
R39 R40 R42 R43 = CRCW040249R9FKED: RES, 49.9 ohm, 1%, 0.063W, 0402; Manufacturer: Vishay-Dale; CompType: Resistor; Value_Code: 49R9; Tolerance_%: 1; Power_W: 0.063; VDC_V: 50; TempCo: 100 ppm/C; EIA_Code: E96; U/M: EA
R41 R44 R45 = CRCW06030000Z0EA: as R12 on sheet Pg3
R54-R57 = RC0603FR-0775RL: RES, 75.0 ohm, 1%, 0.1W, 0603; Manufacturer: Yageo America; CompType: Resistor; Res_ohm: 75; Value_Code: 75R0; Tolerance_%: 1; Power_W: 0.1; VDC_V: 150; TempCo: 200 ppm/C; EIA_Code: E96; U/M: EA
R58 = CRCW12061M00JNEA: RES, 1.0Meg ohm, 5%, 0.25W, 1206; Manufacturer: Vishay-Dale; CompType: Resistor; Res_ohm: 1000000; Value_Code: 1M00; Tolerance_%: 5; Power_W: 0.25; VDC_V: 200; TempCo: 200 ppm/C; EIA_Code: E24; U/M: EA
T1 = HX1198FNL: TRANSFORMER, MDL, XFMR SGL ETHR LAN, SOIC-16; Manufacturer: PULSE ELECTRONICS; SymbolCreator: x0199378

## Sheet Pg6.SchDoc
size 431 x 279 mm; DocumentNumber: 6; SheetNumber: 6; SheetTotal: 9
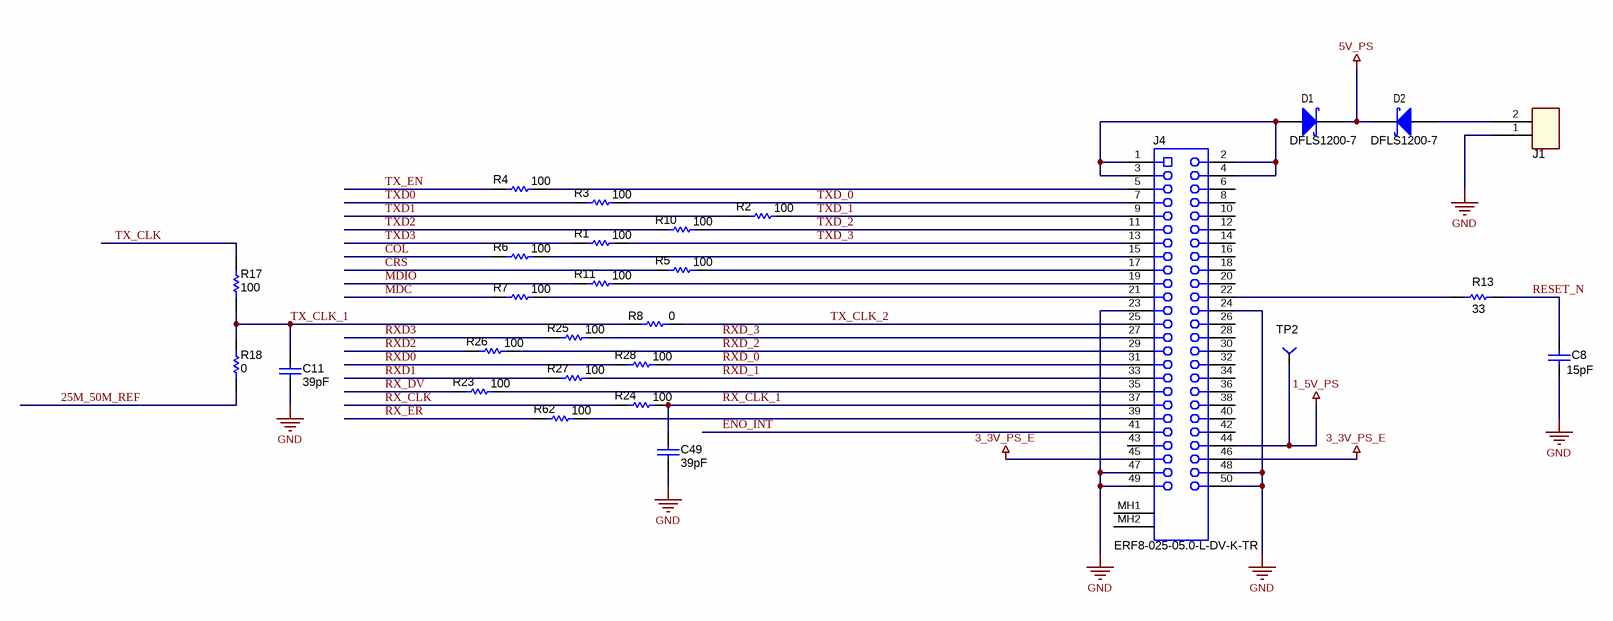
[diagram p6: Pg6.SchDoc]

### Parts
C8  ValueDisplayed: 15pF  [0402]  (hidden comment: C1005C0G1H150J050BA)
C11  ValueDisplayed: 39pF  [0402]  (hidden comment: GRM1555C1E390JA01D)
C49  ValueDisplayed: 39pF  [0402]  (hidden comment: GRM1555C1E390JA01D)
D1  DFLS1200-7  [powerDI123]
D2  DFLS1200-7  [powerDI123]
J1  CON-OSTVN02A150  [CN2_MTB_P100_PD80_D1.1_S5.54X6.5_STACK]  (value not drawn)
J4  ERF8-025-05.0-L-DV-K-TR  [CONN_ERF8-025-05_0-L-DV-L-TR]
R1  value 100  [0402]  (hidden comment: CRCW0402100RJNED)
R2  value 100  [0402]  (hidden comment: CRCW0402100RJNED)
R3  value 100  [0402]  (hidden comment: CRCW0402100RJNED)
R4  value 100  [0402]  (hidden comment: CRCW0402100RJNED)
R5  value 100  [0402]  (hidden comment: CRCW0402100RJNED)
R6  value 100  [0402]  (hidden comment: CRCW0402100RJNED)
R7  value 100  [0402]  (hidden comment: CRCW0402100RJNED)
R8  value 0  [0402]  (hidden comment: CRCW04020000Z0ED)
R10  value 100  [0402]  (hidden comment: CRCW0402100RJNED)
R11  value 100  [0402]  (hidden comment: CRCW0402100RJNED)
R13  value 33  [0402]  (hidden comment: CRCW040233R0JNED)
R17  value 100  [0603]  (hidden comment: CRCW0603100RJNEA)
R18  value 0  [0603]  (hidden comment: CRCW06030000Z0EA)
R23  value 100  [0402]  (hidden comment: CRCW0402100RJNED)
R24  value 100  [0402]  (hidden comment: CRCW0402100RJNED)
R25  value 100  [0402]  (hidden comment: CRCW0402100RJNED)
R26  value 100  [0402]  (hidden comment: CRCW0402100RJNED)
R27  value 100  [0402]  (hidden comment: CRCW0402100RJNED)
R28  value 100  [0402]  (hidden comment: CRCW0402100RJNED)
R62  value 100  [0402]  (hidden comment: CRCW0402100RJNED)
TP2  TP-040_RND  [TP1_PD40_D0.5_S50]  (value not drawn)

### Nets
1_5V_PS: J4.44 TP2.1
3_3V_PS_E: J4.45 J4.46
5V_PS: D1.1(K) D2.1(K)
GND: C8.2 C11.2 C49.2 J1.1 J4.23 J4.24 J4.47 J4.48 J4.49 J4.50
25M_50M_REF: R18.2
COL: R6.1
CRS: R5.1
ENO_INT: J4.41
MDC: R7.1
MDIO: R11.1
RESET_N: C8.1 R13.2
RX_CLK: R24.1
RX_CLK_1: C49.1 J4.37 R24.2
RX_DV: R23.1
RX_ER: R62.1
RXD0: R28.1
RXD1: R27.1
RXD2: R26.1
RXD3: R25.1
RXD_0: J4.31 R28.2
RXD_1: J4.33 R27.2
RXD_2: J4.29 R26.2
RXD_3: J4.27 R25.2
TX_CLK: R17.1
TX_CLK_1: C11.1 R8.1 R17.2 R18.1
TX_CLK_2: J4.25 R8.2
TX_EN: R4.1
TXD0: R3.1
TXD1: R2.1
TXD2: R10.1
TXD3: R1.1
TXD_0: J4.7 R3.2
TXD_1: J4.9 R2.2
TXD_2: J4.11 R10.2
TXD_3: J4.13 R1.2
NetD1_2: D1.2(A) J4.1 J4.2 J4.3 J4.4
NetD2_2: D2.2(A) J1.2
NetJ4_5: J4.5 R4.2
NetJ4_15: J4.15 R6.2
NetJ4_17: J4.17 R5.2
NetJ4_19: J4.19 R11.2
NetJ4_21: J4.21 R7.2
NetJ4_22: J4.22 R13.1
NetJ4_35: J4.35 R23.2
NetJ4_39: J4.39 R62.2

Not connected (* = marked no-connect by the designer): J4 6 8 10 12 14 16 18 20 26 28 30 32 34 36 38 40 42 43 MH1(51) MH2(52)

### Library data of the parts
C8 = GRM1555C1H150JA01D: CAP CER 15PF 50V 5% NP0 0402; Manufacturer: TDK Corporation; Polarized: N; CompType: Capacitor; U/M: EA; Cap_F: 0.000000000015; Tolerance_%: 5; Value1: Unknown; VDC_V: 50; TempCo: C0G/NP0; TaMin_C: -55; TaMax_C: 125
C11 C49 = GRM1555C1E390JA01D: CAP, CERM, 39pF, 25V, +/-5%, C0G/NP0, 0402; Manufacturer: MuRata; Polarized: N; CompType: Capacitor; U/M: EA; Cap_F: 0.000000000039; Tolerance_%: 5; Value1: Unknown; VDC_V: 25; TaMin_C: -55; TaMax_C: 125
D1 D2 = DFLS1200-7: Diode, Schottky, 200V, 1A, PowerDI123; Manufacturer: Diodes Inc.; U/M: EA; Vf_V: 0.85; Value2: 0.85V; Io_A: 1; Vr_V: 200; TJmax_C: 175; RJC_CperW: 7
J1 = CON-OSTVN02A150: CONN TERM BLOCK 2.54MM 2POS PCB; Manufacturer: On Shore Technology Inc; SymbolCreator: x0120606; CompType: Terminal Block
J4 = ERF8-025-05.0-L-DV-K-TR: Receptacle, 0.8mm, 25x2, SMT; Manufacturer: Samtec; SymbolCreator: a0412235; CompType: Connector; U/M: EA
R1-R7 R10 R11 R23-R28 R62 = CRCW0402100RJNED: RES, 100 ohm, 5%, 0.063W, 0402; Manufacturer: Vishay-Dale; CompType: Resistor; Value_Code: 100R; Tolerance_%: 5; Power_W: 0.063; VDC_V: 50; TempCo: 200 ppm/C; EIA_Code: E24; U/M: EA
R8 = CRCW04020000Z0ED: RES, 0 ohm, 5%, 0.063W, 0402; Manufacturer: Vishay-Dale; CompType: Resistor; Value_Code: 0000; Tolerance_%: 5; Power_W: 0.063; VDC_V: 50; TempCo: 200 ppm/C; EIA_Code: E24; U/M: EA
R13 = CRCW040233R0JNED: RES, 33 ohm, 5%, 0.063W, 0402; Manufacturer: Vishay-Dale; CompType: Resistor; Value_Code: 33R0; Tolerance_%: 5; Power_W: 0.063; VDC_V: 50; TempCo: 200 ppm/C; EIA_Code: E24; U/M: EA
R17 = CRCW0603100RJNEA: RES, 100 ohm, 5%, 0.1W, 0603; Manufacturer: Vishay-Dale; CompType: Resistor; Value_Code: 100R; Tolerance_%: 5; Power_W: 0.1; VDC_V: 75; TempCo: 200 ppm/C; EIA_Code: E24; U/M: EA
R18 = CRCW06030000Z0EA: as R12 on sheet Pg3
TP2 = TP-040_RND: Test Point 40mil pad 20mil drill; Manufacturer: STD; Description: Test Point, O.040 Hole; Value: STD

## Sheet Pg7.SchDoc
size 431 x 279 mm; DocumentNumber: 7; SheetNumber: 7; SheetTotal: 9
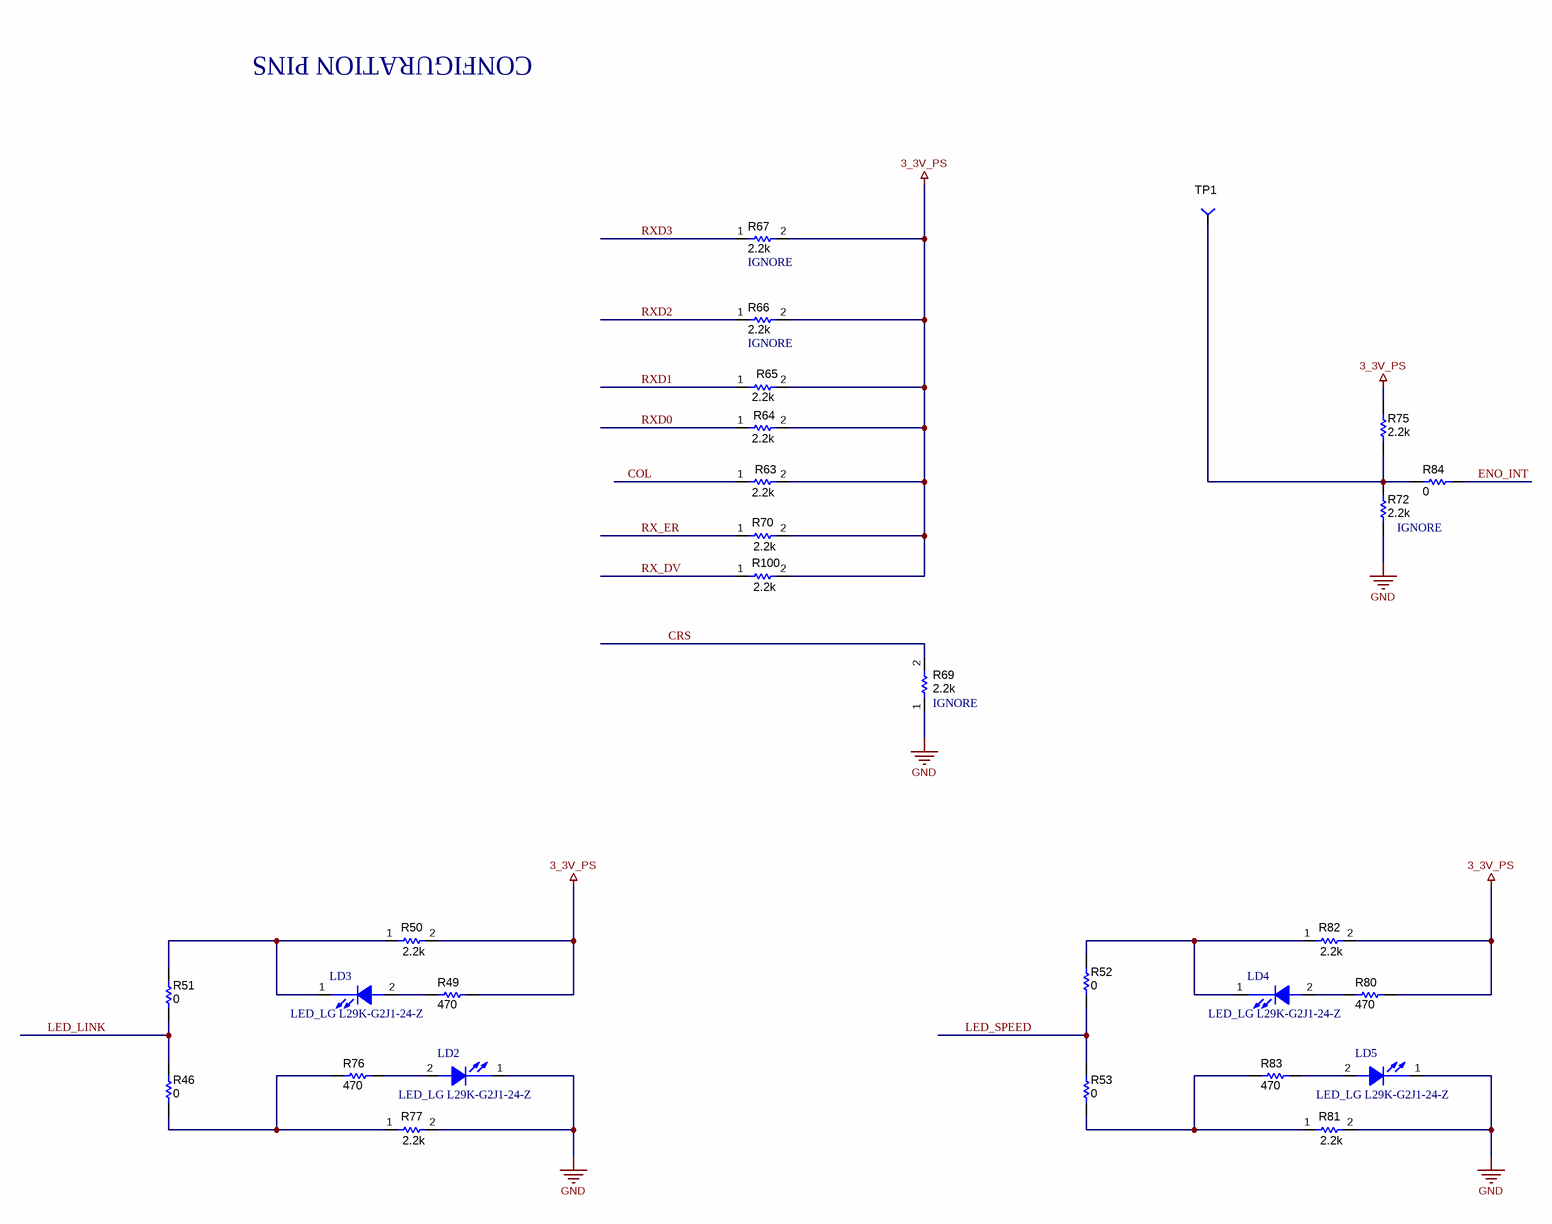
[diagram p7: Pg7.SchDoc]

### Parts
LD2  LED_LG L29K-G2J1-24-Z  [LED0603AA]
LD3  LED_LG L29K-G2J1-24-Z  [LED0603AA]
LD4  LED_LG L29K-G2J1-24-Z  [LED0603AA]
LD5  LED_LG L29K-G2J1-24-Z  [LED0603AA]
R46  value 0  [0603]  (hidden comment: CRCW06030000Z0EA)
R49  value 470  [0603]  (hidden comment: RC0603FR-07470RL)
R50  value 2.2k  [0402]  (hidden comment: CRCW04022K20JNED)
R51  value 0  [0603]  (hidden comment: CRCW06030000Z0EA)
R52  value 0  [0603]  (hidden comment: CRCW06030000Z0EA)
R53  value 0  [0603]  (hidden comment: CRCW06030000Z0EA)
R63  value 2.2k  [0402]  (hidden comment: CRCW04022K20JNED)
R64  value 2.2k  [0402]  (hidden comment: CRCW04022K20JNED)
R65  value 2.2k  [0402]  (hidden comment: CRCW04022K20JNED)
R66  value 2.2k  [0402]  (hidden comment: CRCW04022K20JNED)
R67  value 2.2k  [0402]  (hidden comment: CRCW04022K20JNED)
R69  value 2.2k  [0402]  (hidden comment: CRCW04022K20JNED)
R70  value 2.2k  [0402]  (hidden comment: CRCW04022K20JNED)
R72  value 2.2k  [0402]  (hidden comment: CRCW04022K20JNED)
R75  value 2.2k  [0402]  (hidden comment: CRCW04022K20JNED)
R76  value 470  [0603]  (hidden comment: RC0603FR-07470RL)
R77  value 2.2k  [0402]  (hidden comment: CRCW04022K20JNED)
R80  value 470  [0603]  (hidden comment: RC0603FR-07470RL)
R81  value 2.2k  [0402]  (hidden comment: CRCW04022K20JNED)
R82  value 2.2k  [0402]  (hidden comment: CRCW04022K20JNED)
R83  value 470  [0603]  (hidden comment: RC0603FR-07470RL)
R84  value 0  [0603]  (hidden comment: CRCW06030000Z0EA)
R100  value 2.2k  [0402]  (hidden comment: CRCW04022K20JNED)
TP1  TP-040_RND  [TP1_PD40_D0.5_S50]  (value not drawn)

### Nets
3_3V_PS: R49.2 R50.2 R63.2 R64.2 R65.2 R66.2 R67.2 R70.2 R75.2 R80.2 R82.2 R100.2
GND: LD2.1(C) LD5.1(C) R69.1 R72.1 R77.2 R81.2
COL: R63.1
CRS: R69.2
ENO_INT: R84.1
LED_LINK: R46.2 R51.1
LED_SPEED: R52.1 R53.2
RX_DV: R100.1
RX_ER: R70.1
RXD0: R64.1
RXD1: R65.1
RXD2: R66.1
RXD3: R67.1
NetLD2_2: LD2.2(A) R76.2
NetLD3_1: LD3.1(C) R50.1 R51.2
NetLD3_2: LD3.2(A) R49.1
NetLD4_1: LD4.1(C) R52.2 R82.1
NetLD4_2: LD4.2(A) R80.1
NetLD5_2: LD5.2(A) R83.2
NetR46_1: R46.1 R76.1 R77.1
NetR53_1: R53.1 R81.1 R83.1
NetR72_2: R72.2 R75.1 R84.2 TP1.1

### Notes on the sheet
- CONFIGURATION PINS

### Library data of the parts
LD2-LD5 = LED_LG L29K-G2J1-24-Z: LED SmartLED Green 570NM; Manufacturer: OSRAM; SymbolCreator: x0120606
R46 R51-R53 R84 = CRCW06030000Z0EA: as R12 on sheet Pg3
R49 R76 R80 R83 = RC0603FR-07470RL: RES, 470 ohm, 1%, 0.1W, 0603; Manufacturer: Yageo America; CompType: Resistor; Value_Code: 470R; Tolerance_%: 1; Power_W: 0.1; VDC_V: 150; TempCo: 200 ppm/C; U/M: EA
R50 R63-R67 R69 R70 R72 R75 R77 R81 R82 R100 = CRCW04022K20JNED: as R16 on sheet Pg3
TP1 = TP-040_RND: as TP2 on sheet Pg6

## Sheet Pg8.SchDoc
size 431 x 279 mm; Date: Not shown in title block; ApprovedBy: Not shown in title block; CheckedBy: Not shown in title block; Author: Not shown in title block; CompanyName: Not shown in title block; Engineer: Not shown in title block; Organization: Not shown in title block; Address1: Not shown in title block; Address2: Not shown in title block; Address3: Not shown in title block; Address4: Not shown in title block; DocumentNumber: 8; Revision: Use project parameter SCH_Rev; SheetNumber: 8; SheetTotal: 9; PageSetup: Record=PageOptions|CenterHorizontal=True|CenterVertical=True|PrintScale=0.59|XCorrection=1.00|YCorrection=1.00|PrintKind=0|BorderSize=5000000|LeftOffset=0|BottomOffset=0|Orientation=2|PaperLength=1000|PaperWidth=1000|Scale=100|PaperSource=15|PrintQuality=600|MediaType=1|DitherType=10|PaperKind=Letter|PrintScaleMode=1
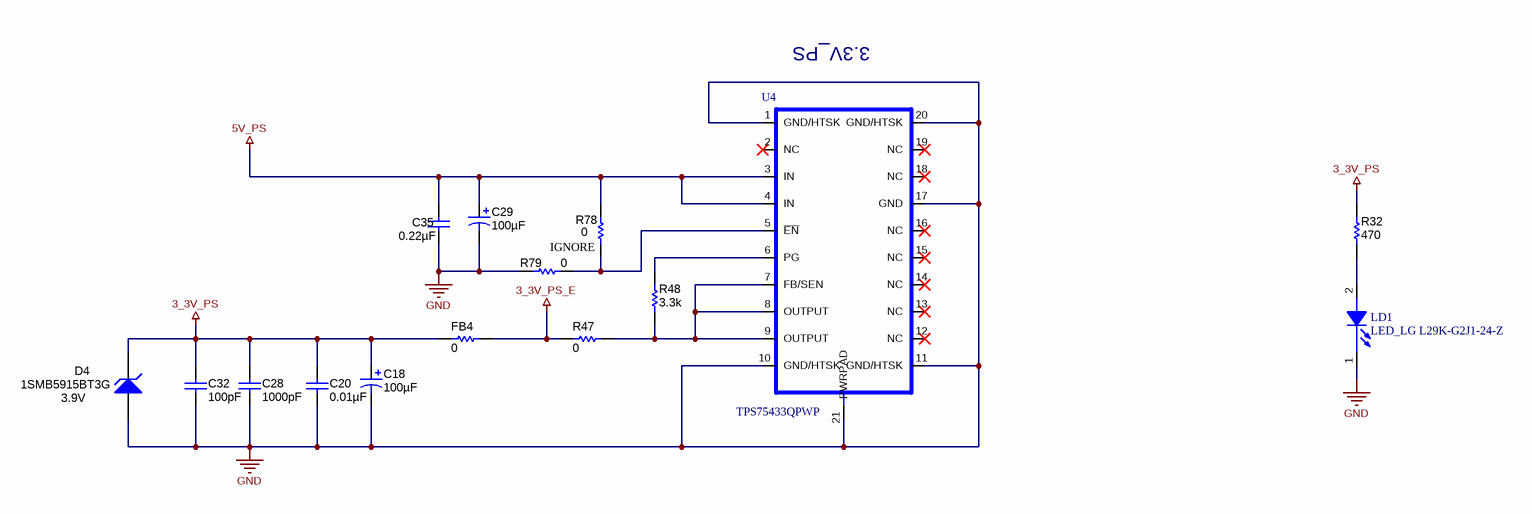
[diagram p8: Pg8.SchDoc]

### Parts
C18  ValueDisplayed: 100µF  [7343-31]  (hidden comment: 293D107X0010D2TE3)
C20  ValueDisplayed: 0.01µF  [0402]  (hidden comment: GCM155R71H103KA55D)
C28  ValueDisplayed: 1000pF  [0402]  (hidden comment: GRM155R61E102KA01D)
C29  ValueDisplayed: 100µF  [7343-31]  (hidden comment: 293D107X0010D2TE3)
C32  ValueDisplayed: 100pF  [0402]  (hidden comment: CC0402KRX7R9BB101)
C35  ValueDisplayed: 0.22µF  [0603]  (hidden comment: GRM188R71C224KA01D)
D4  1SMB5915BT3G  value 3.9V  [SMB]
FB4  value 0  [0603]  (hidden comment: CRCW06030000Z0EA)
LD1  LED_LG L29K-G2J1-24-Z  [LED0603AA]
R32  value 470  [0603]  (hidden comment: RC0603FR-07470RL)
R47  value 0  [0603]  (hidden comment: CRCW06030000Z0EA)
R48  value 3.3k  [0402]  (hidden comment: CRCW04023K30JNED)
R78  value 0  [0603]  (hidden comment: CRCW06030000Z0EA)
R79  value 0  [0603]  (hidden comment: CRCW06030000Z0EA)
U4  TPS75433QPWP  [PWP20]

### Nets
3_3V_PS: C18.1(+) C20.1 C28.1 C32.1 D4.1(K) FB4.2 R32.2
3_3V_PS_E: FB4.1 R47.2
5V_PS: C29.1(+) C35.2 R78.1 U4.3(IN) U4.4(IN)
GND: C18.2(-) C20.2 C28.2 C29.2(-) C32.2 C35.1 D4.2(A) LD1.1(C) R79.1 U4.1(GND/HTSK) U4.10(GND/HTSK) U4.11(GND/HTSK) U4.17(GND) U4.20(GND/HTSK) U4.21(PWRPAD)
NetLD1_2: LD1.2(A) R32.1
NetR47_1: R47.1 R48.2 U4.7(FB/SEN) U4.8(OUTPUT) U4.9(OUTPUT)
NetR48_1: R48.1 U4.6(PG)
NetR78_2: R78.2 R79.2 U4.5(~{EN})

Not connected (* = marked no-connect by the designer): U4 2(NC)* 12(NC)* 13(NC)* 14(NC)* 15(NC)* 16(NC)* 18(NC)* 19(NC)*

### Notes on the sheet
- 3.3V_PS

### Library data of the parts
C18 C29 = 293D107X0010D2TE3: CAP, TA, 100uF, 10V, +/-20%, 0.6 ohm, SMD; Manufacturer: Vishay-Sprague; Polarized: Y; CompType: Capacitor; U/M: EA; Cap_F: 0.0001; Tolerance_%: 20; Value1: 0.6 ohm; VDC_V: 10; ESR_Ohm: 0.6; IRMS_A: 0.5; TaMin_C: -55; TaMax_C: 125; Cap_Case: D
C20 = GCM155R71H103KA55D: as C10 on sheet Pg3
C28 = GRM155R61E102KA01D: as C46 on sheet Pg3
C32 = CC0402KRX7R9BB101: as C12 on sheet Pg3
C35 = GRM188R71C224KA01D: CAP, CERM, 0.22uF, 16V, +/-10%, X7R, 0603; Manufacturer: MuRata; Polarized: N; CompType: Capacitor; U/M: EA; Cap_F: 0.00000022; Tolerance_%: 10; Value1: Unknown; VDC_V: 16; TaMin_C: -55; TaMax_C: 125
D4 = 1SMB5915BT3G: Diode, Zener, 3.9V, 550mW, SMB; Manufacturer: ON Semiconductor; SymbolCreator: a0412235; U/M: EA; Power_W: 0.55; Vz_V: 3.9; Value1: 0.55W; RJA_CperW: 226
FB4 R47 R78 R79 = CRCW06030000Z0EA: as R12 on sheet Pg3
LD1 = LED_LG L29K-G2J1-24-Z: as LD2 on sheet Pg7
R32 = RC0603FR-07470RL: as R49 on sheet Pg7
R48 = CRCW04023K30JNED: RES, 3.3k ohm, 5%, 0.063W, 0402; Manufacturer: Vishay-Dale; CompType: Resistor; Res_ohm: 3300; Value_Code: 3k30; Tolerance_%: 5; Power_W: 0.063; VDC_V: 50; TempCo: 200 ppm/C; EIA_Code: E24; U/M: EA
U4 = TPS75433QPWP: IC, Low Dropout Voltage Regulator, 3.3 V, 2.0 A; Manufacturer: Texas Instruments; Alternate Manufacturer: None; Area: 96000

## Sheet Pg9 Hardware.SchDoc
size 431 x 279 mm; Date: Not shown in title block; ApprovedBy: Not shown in title block; CheckedBy: Not shown in title block; Author: Not shown in title block; CompanyName: Not shown in title block; Engineer: Not shown in title block; Organization: Not shown in title block; Address1: Not shown in title block; Address2: Not shown in title block; Address3: Not shown in title block; Address4: Not shown in title block; DocumentNumber: 9; Revision: Use project parameter SCH_Rev; SheetNumber: 9; SheetTotal: 9; PageSetup: Record=PageOptions|CenterHorizontal=True|CenterVertical=True|PrintScale=1.00|XCorrection=1.00|YCorrection=1.00|PrintKind=0|BorderSize=5000000|LeftOffset=0|BottomOffset=0|Orientation=2|PaperLength=1000|PaperWidth=1000|Scale=100|PaperSource=15|PrintQuality=600|MediaType=1|DitherType=10|PaperKind=Letter|PrintScaleMode=1
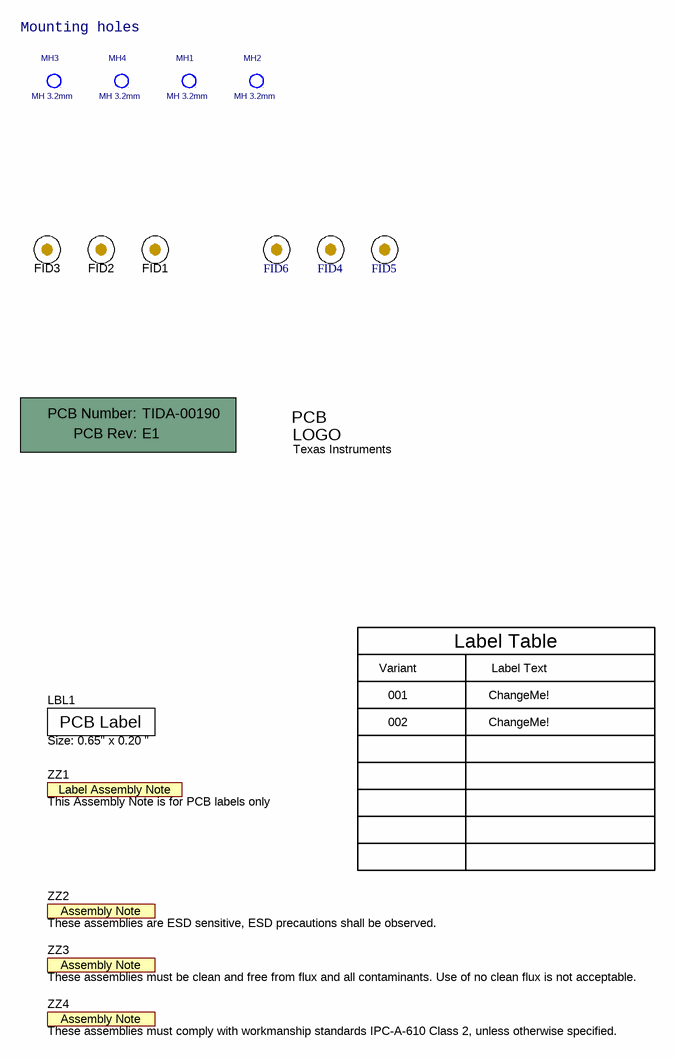
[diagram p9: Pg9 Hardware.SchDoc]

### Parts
!PCB1  Printed Circuit Board  (value not drawn)  (mechanical)
FID1  Fiducial  [Fiducial10-20]  (value not drawn)
FID2  Fiducial  [Fiducial10-20]  (value not drawn)
FID3  Fiducial  [Fiducial10-20]  (value not drawn)
FID4  Fiducial  [Fiducial10-30]  (value not drawn)
FID5  Fiducial  [Fiducial10-30]  (value not drawn)
FID6  Fiducial  [Fiducial10-30]  (value not drawn)
LBL1  Size: 0.65" x 0.20 "  [Label_650x200]
Logo1  Texas Instruments  [TI_Stacked_SolderMask_Small]  (no BOM)
MH1  MH 3.2mm  [MH3.2_H5_W6_KO8_STARHEAD]
MH2  MH 3.2mm  [MH3.2_H5_W6_KO8_STARHEAD]
MH3  MH 3.2mm  [MH3.2_H5_W6_KO8_STARHEAD]
MH4  MH 3.2mm  [MH3.2_H5_W6_KO8_STARHEAD]
ZZ1  This Assembly Note is for PCB labels only  [AssemblyNoteLabel]  (no BOM)
ZZ2  These assemblies are ESD sensitive, ESD precautions shall be observed.  [AssemblyNote]  (no BOM)
ZZ3  These assemblies must be clean and free from flux and all contaminants. Use of no clean flux is not acceptable.  [AssemblyNote]  (no BOM)
ZZ4  These assemblies must comply with workmanship standards IPC-A-610 Class 2, unless otherwise specified.  [AssemblyNote]  (no BOM)

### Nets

Not connected (* = marked no-connect by the designer): MH1 1; MH2 1; MH3 1; MH4 1

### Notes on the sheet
- Mounting holes
- Variant
- Label Table
- Label Text
- 001
- 002
- ChangeMe!

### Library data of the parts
!PCB1 = PCB: Manufacturer: Any; PartNumber: TIDA-00190; SymbolCreator: a0412235
FID1-FID6 = Fiducial: Fiducial mark.  There is nothing to buy or mount.; SymbolCreator: codlsc
LBL1 = THT-14-423-10: Thermal Transfer Printable Labels, 0.650" W x 0.200" H - 10,000 per roll; Manufacturer: Brady; SymbolCreator: a0412235; CompType: Label
Logo1 = TI_Logo: Texas Instrument Corporate Signature; SymbolCreator: codlsc
MH1-MH4 = MH 3_0.5MM: Mountin hole, NPTH Drill 3.2mm
ZZ1 = AssemblyNoteLabel: SymbolCreator: a0412235
ZZ2-ZZ4 = AssemblyNote: SymbolCreator: codlsc

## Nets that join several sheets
3_3V_PS: Pg3 (FB3.1 R21.1 R38.1 R74.1), Pg4 (C44.2 C45.2), Pg5 (R45.2), Pg7 (12 pins), Pg8 (7 pins)
3_3V_PS_E: Pg6 (J4.45 J4.46), Pg8 (FB4.1 R47.2)
5V_PS: Pg4 (C1.1 C5.1 U1.4), Pg6 (D1.1 D2.1), Pg8 (5 pins)
GND: Pg3 (31 pins), Pg4 (14 pins), Pg5 (10 pins), Pg6 (10 pins), Pg7 (6 pins), Pg8 (15 pins)
25M_50M_REF: Pg3 (R61.1), Pg6 (R18.2)
CLOCK_Y3: Pg3 (U5.1 X1.3), Pg4 (R14.2 R15.2)
COL: Pg3 (U15.35), Pg6 (R6.1), Pg7 (R63.1)
CRS: Pg3 (U15.33), Pg6 (R5.1), Pg7 (R69.2)
ENO_INT: Pg6 (J4.41), Pg7 (R84.1)
LED_LINK: Pg3 (U15.22), Pg7 (R46.2 R51.1)
LED_SPEED: Pg3 (U15.21), Pg7 (R52.1 R53.2)
MDC: Pg3 (U15.25), Pg6 (R7.1)
MDIO: Pg3 (R74.2 U15.24), Pg6 (R11.1)
RDM_B: Pg3 (U15.11), Pg5 (R40.2 T1.8)
RDP_B: Pg3 (U15.12), Pg5 (R42.2 T1.6)
RESET_N: Pg3 (R19.2 U15.23), Pg6 (C8.1 R13.2)
RX_CLK: Pg3 (U15.31), Pg6 (R24.1)
RX_DV: Pg3 (U15.32), Pg6 (R23.1), Pg7 (R100.1)
RX_ER: Pg3 (U15.34), Pg6 (R62.1), Pg7 (R70.1)
RXD0: Pg3 (U15.36), Pg6 (R28.1), Pg7 (R64.1)
RXD1: Pg3 (U15.37), Pg6 (R27.1), Pg7 (R65.1)
RXD2: Pg3 (U15.38), Pg6 (R26.1), Pg7 (R66.1)
RXD3: Pg3 (U15.39), Pg6 (R25.1), Pg7 (R67.1)
TDM_A: Pg3 (U15.14), Pg5 (R39.2 T1.3)
TDP_A: Pg3 (U15.15), Pg5 (R43.2 T1.1)
TX_CLK: Pg3 (U15.2), Pg6 (R17.1)
TX_EN: Pg3 (U15.3), Pg6 (R4.1)
TXD0: Pg3 (U15.4), Pg6 (R3.1)
TXD1: Pg3 (U15.5), Pg6 (R2.1)
TXD2: Pg3 (R68.2 U15.6), Pg6 (R10.1)
TXD3: Pg3 (R71.2 U15.7), Pg6 (R1.1)

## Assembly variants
001: not fitted C1 C2 C3 C4 C5 C7 C9 C10 C12 C41 C42 C43 C44 C45 C46 C51 FB1 FB2 FB3 FID1 FID2 FID3 FID4 FID5 FID6 J2 LBL1 R9 R12 R14 R15 R16 R18 R29 R31 R36 R46 R47 R52 R59 R60 R63 R66 R67 R68 R69 R71 R72 R78 U1 U2 U5 X1 Y1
